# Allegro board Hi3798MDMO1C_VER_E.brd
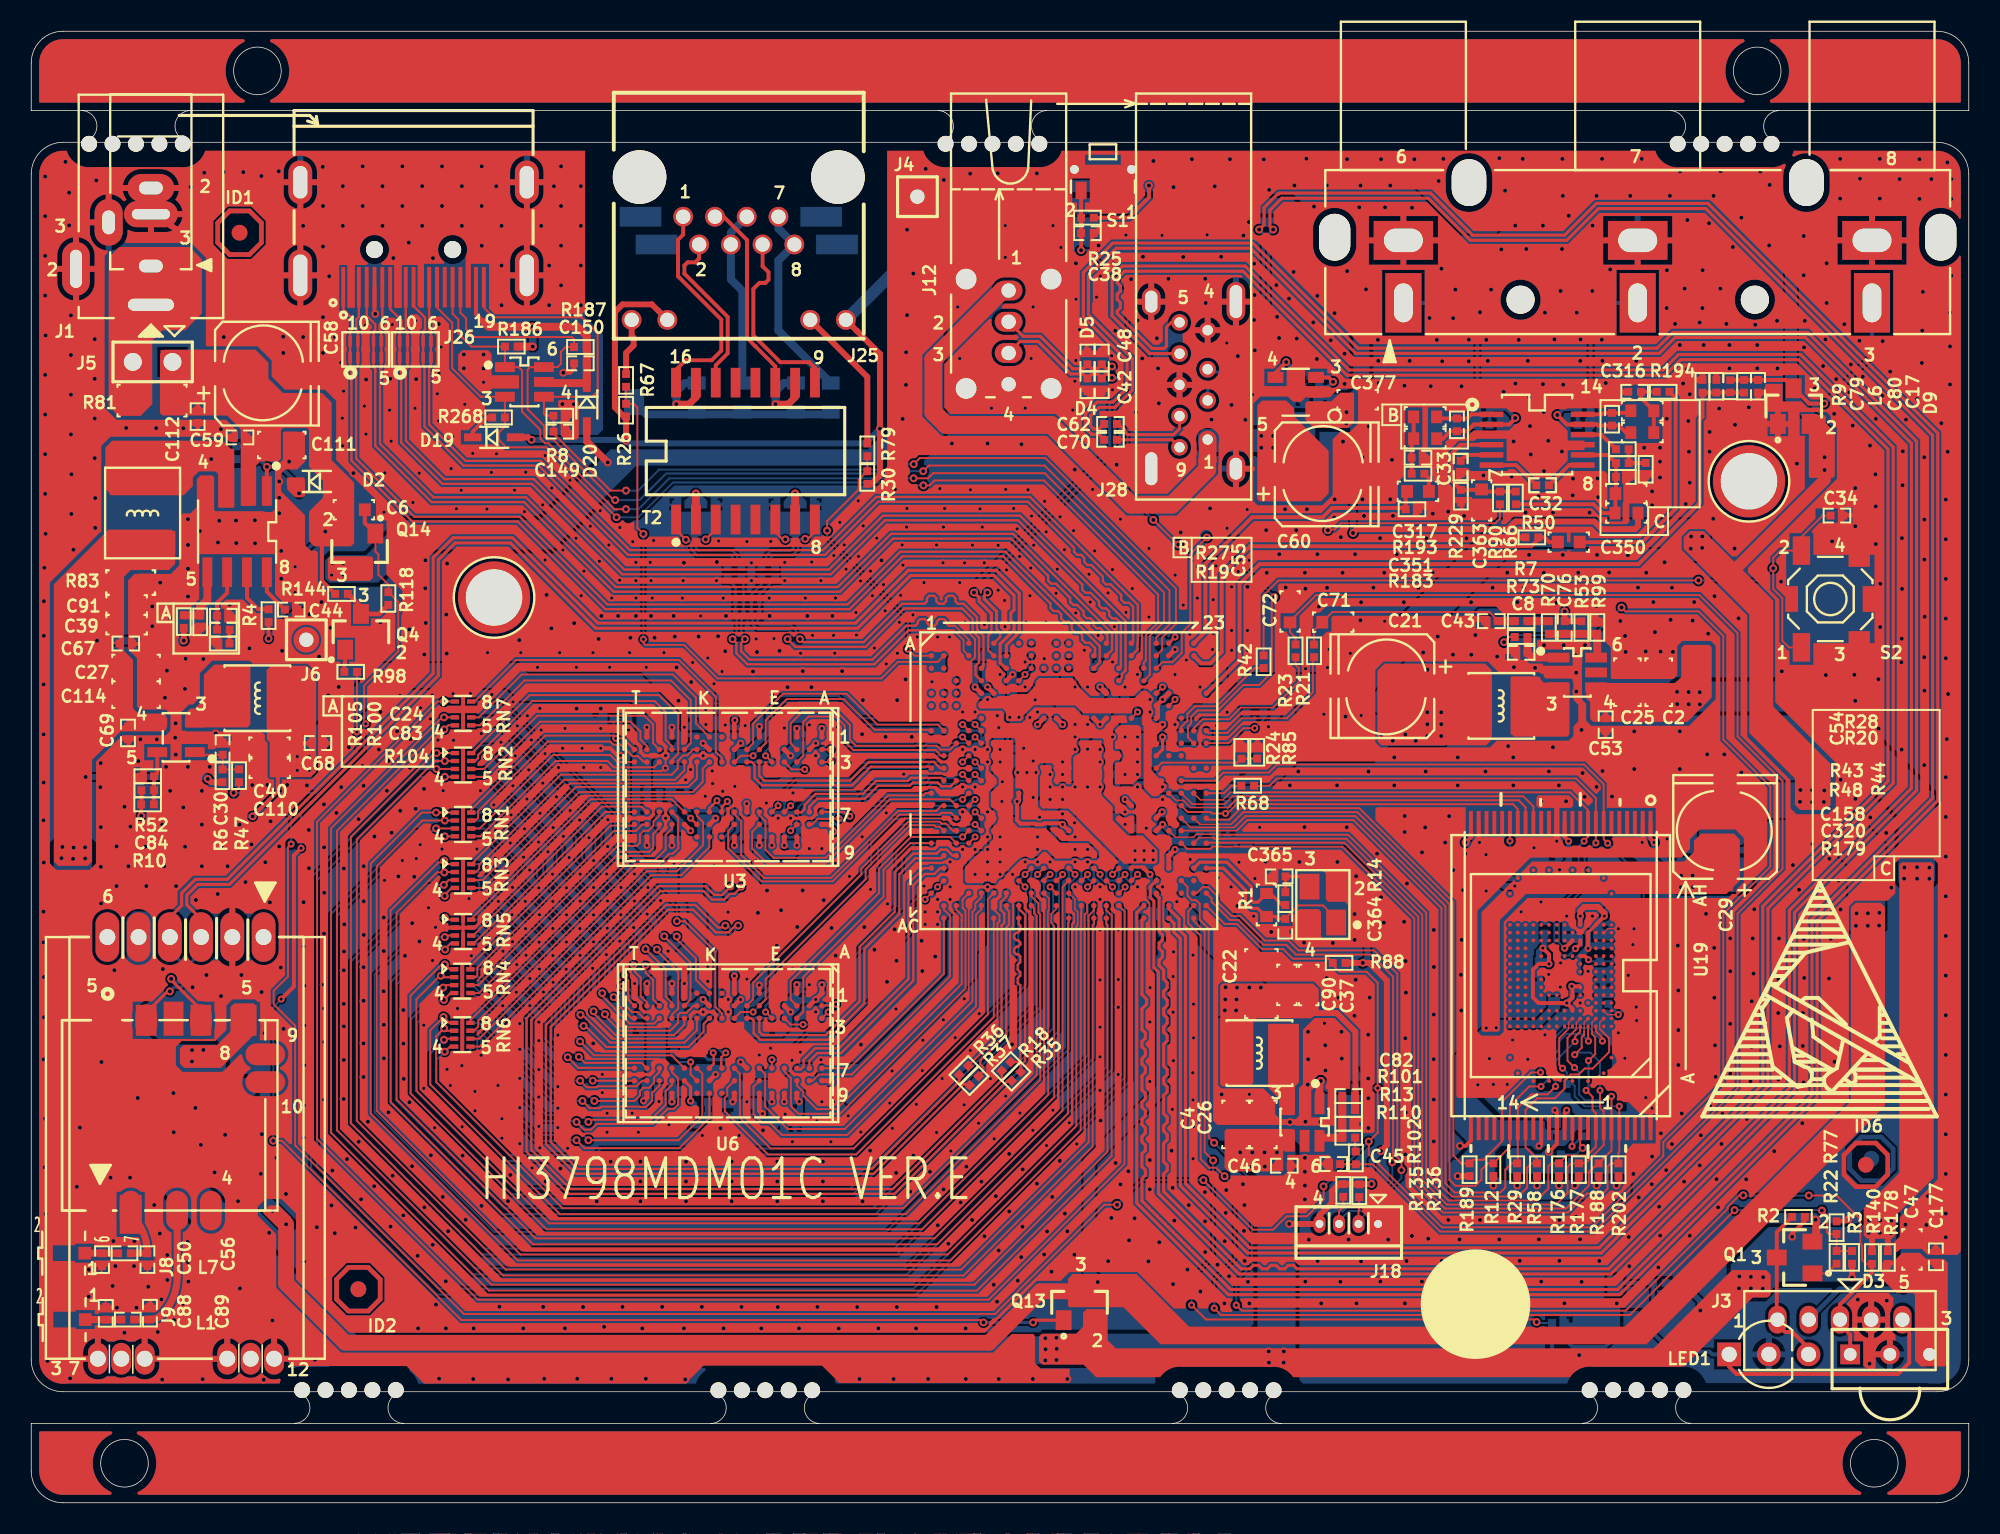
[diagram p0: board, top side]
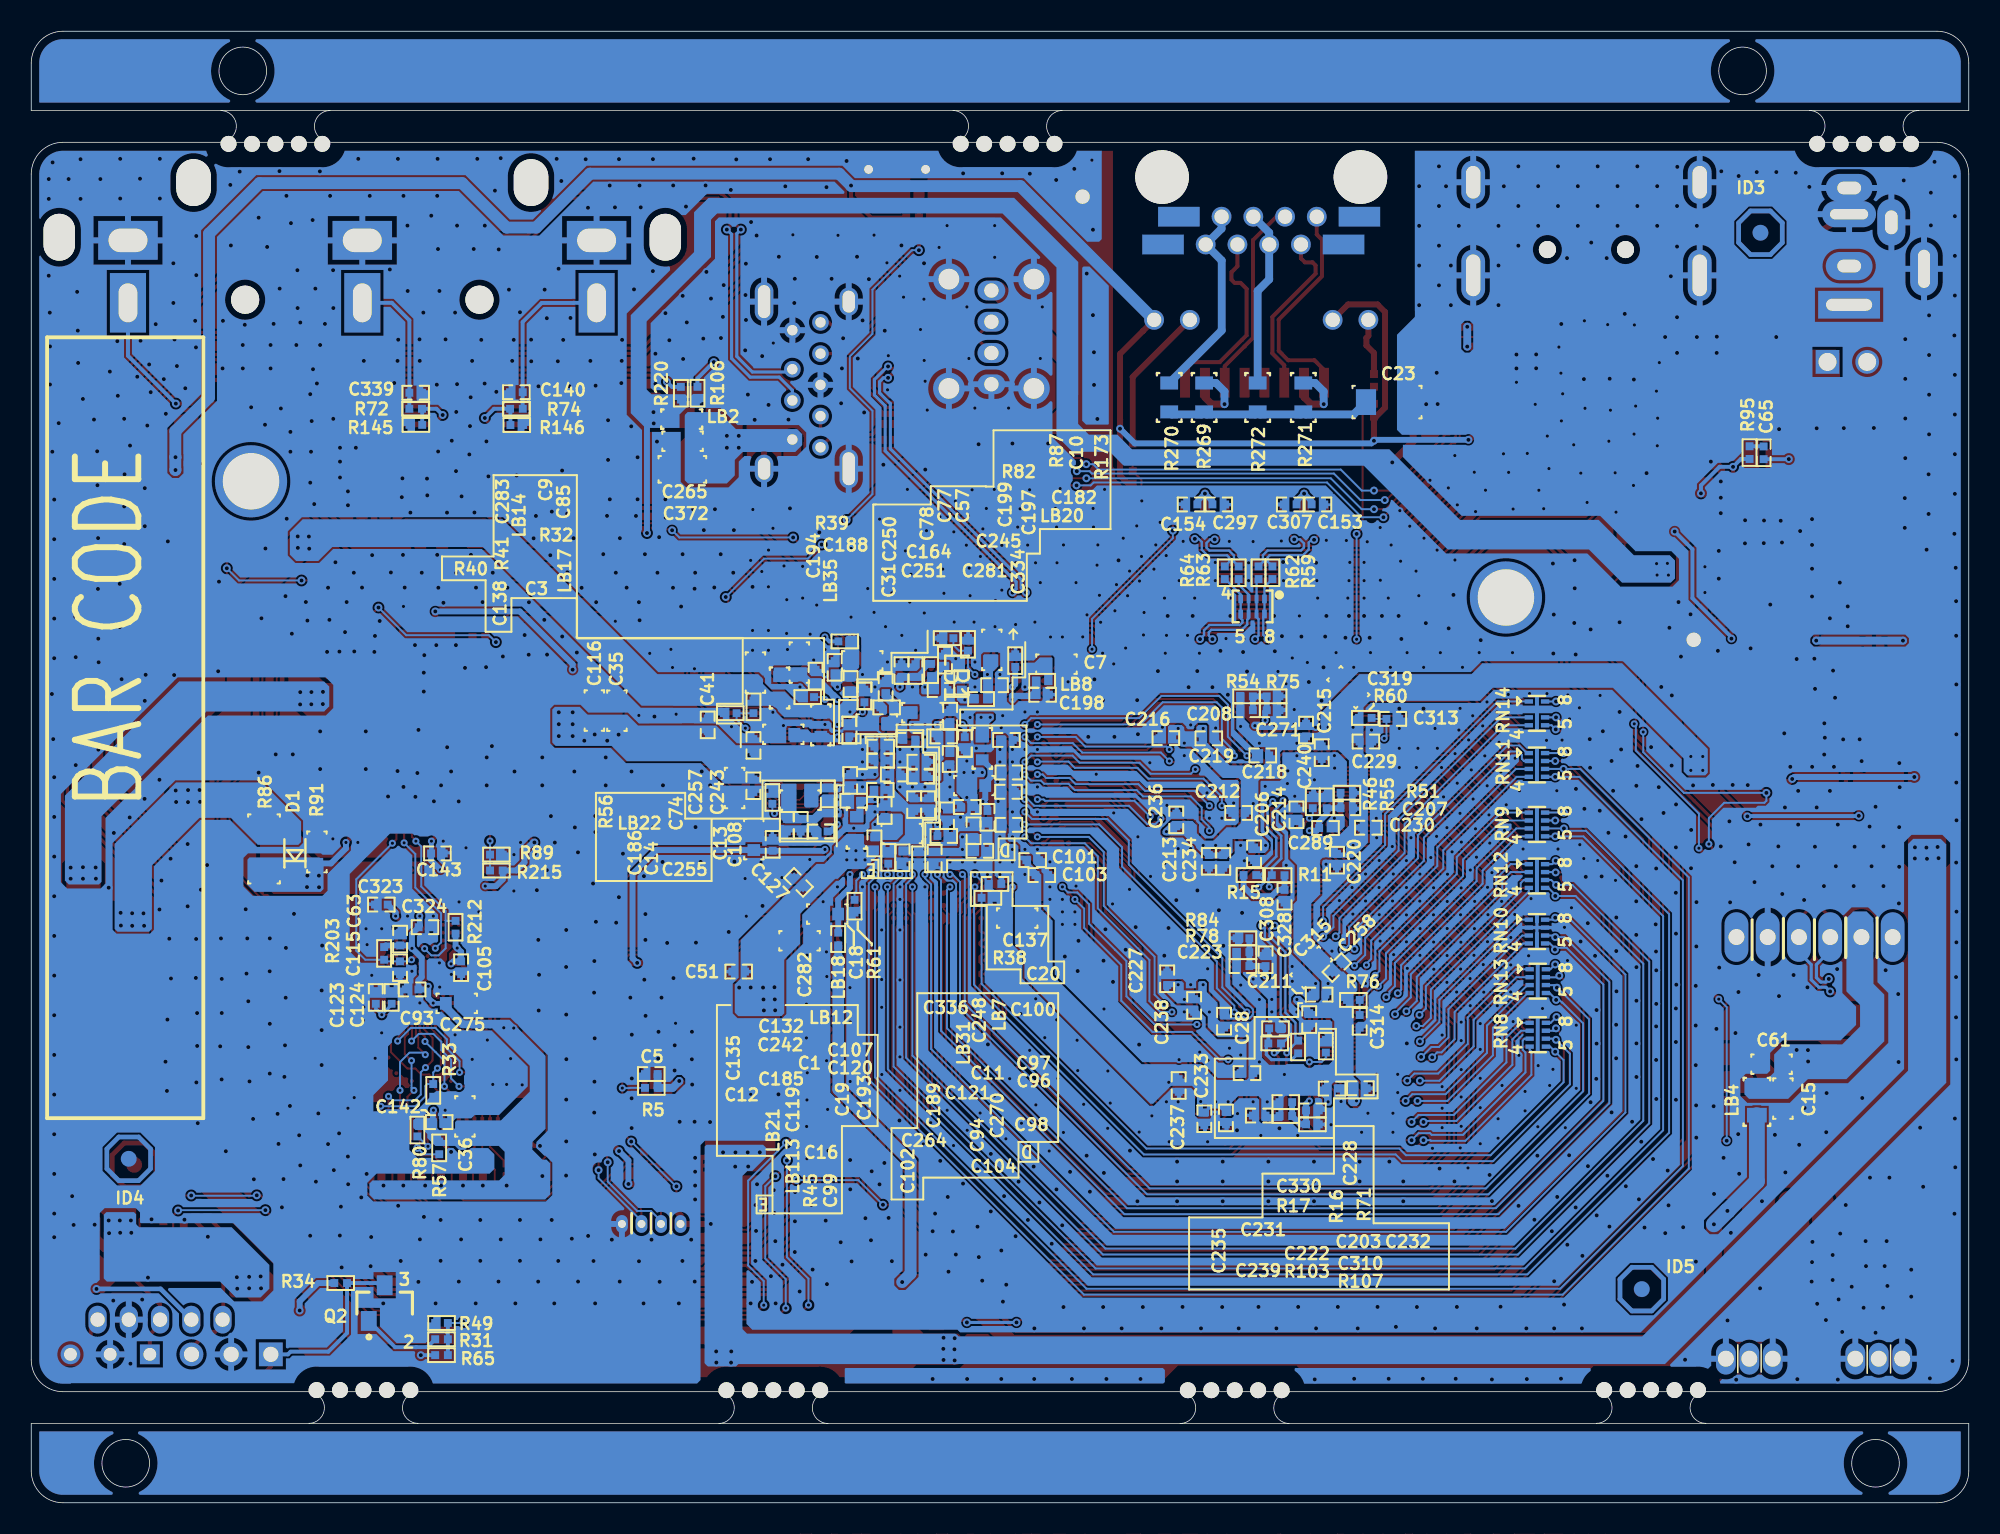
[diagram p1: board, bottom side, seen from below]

Outline 124.03 x 94.22 mm; copper layers: TOP, BOTTOM. Coordinates in mm from the lower left corner of the outline.
Outline path: circle c5.97,2.53 r1.52 ; circle c14.48,91.68 r1.52 ; circle c110.49,91.68 r1.52 ; circle c117.98,2.53 r1.52 ; 0,92.19 arc(0.6,93.63) 2.03,94.22 122,94.22 arc(123.44,93.63) 124.03,92.19 124.03,89.14 0,89.14 0,92.19 ; 0,85.08 arc(0.6,86.52) 2.03,87.11 122,87.11 arc(123.44,86.52) 124.03,85.08 124.03,9.14 arc(123.44,7.71) 122,7.11 2.03,7.11 arc(0.6,7.71) 0,9.14 0,85.08 ; 0,5.08 124.03,5.08 124.03,2.03 arc(123.44,0.6) 122,0 2.03,0 arc(0.6,0.6) 0,2.03 0,5.08

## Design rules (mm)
constraint set DEFAULT: min track width 0.127
net group $4N904: nets $4N904 $4N905
net group $6N188: nets $6N188 XOUT
net group $7N1940: nets $7N1940 USB_BOOT
net group $8N1694: nets $8N1694 DDR_CLK0P
net group $8N1695: nets $8N1695 DDR_CLK0N
net group $8N1696: nets $8N1696 DDR_CLK1P
net group $8N1697: nets $8N1697 DDR_CLK1N
net group $14N447: nets 5V0_MOS $14N447
net group $14N684: nets $14N684 USB3_TXP
net group $14N685: nets $14N685 USB3_TXN
net group $15N955: nets $15N955 LED_RED
net group $15N957: nets $15N957 LED_GREEN
net group $16N1002: nets $16N1002 $16N1006
net group $16N1003: nets $16N1003 $16N1021
net group $16N1028: nets $16N1028 $16N1029
net group $16N1040: nets $16N1040 $16N1041
net group $17N165: nets $17N165 LED0_BASE
net group $17N170: nets $17N170 LED0_LINK_ACT
net group $17N255: nets $17N255 TX+_PHY0
net group $17N256: nets $17N256 TX-_PHY0
net group $17N257: nets $17N257 RX+_PHY0
net group $17N258: nets $17N258 RX-_PHY0
net group $19N506: nets $19N506 HDMI_TX_CEC
net group AVDD33_ADAC: nets AVDD33_ADAC SPDIF_OUT_BOOT_SEL1
net group CLK: nets NF_RDY0_EMMC_RST NF_REN_EMMC_CLK
net group CVBS: nets CVBS CVBS_OUT
net group DIFFPAIR21: nets $17N178 $17N179
net group DIFFPAIR22: nets $17N175 $17N176
net group DIFFPAIR23: nets USB3_RXN USB3_RXP
net group 00: nets GND
net group 01: nets ADAC_VOUTL ADAC_VOUTR AUDIO_L AUDIO_R
net group 5V0_MOS_HDMI: nets 5V0_MOS_HDMI HDMI_TX_SCL HDMI_TX_SDA
net group $4N593: nets $4N593 $4N687 $4N724 $5N549 STANDBY_PWROFF
net group $4N676: nets 1V1_CPU $4N676 $4N677 $4N894 CPU_CTRL
net group $4N714: nets $4N714 $4N715 $4N716 CORE_CTRL
net group $4N903: nets $4N903 $4N923 $4N925
net group $4N906: nets 5V0 $4N906 $4N944 $5N541 $5N542
net group $16N1000: nets $16N873 $16N998 $16N1000 MUTE_CTRL VDD_AUDIO
net group DDR: nets DDR_ADDR0 DDR_ADDR1 DDR_ADDR2 DDR_ADDR3 DDR_ADDR4 DDR_ADDR5 DDR_ADDR6 DDR_ADDR7 DDR_ADDR8 DDR_ADDR9 DDR_ADDR10 DDR_ADDR11 DDR_ADDR12 DDR_ADDR13 DDR_ADDR14 DDR_ADDR15 DDR_BA0 DDR_BA1 DDR_BA2 DDR_CASN DDR_CKE DDR_CSN DDR_DM0 DDR_DM1 DDR_DM2 DDR_DM3 DDR_DQ0 DDR_DQ1 DDR_DQ2 DDR_DQ3 DDR_DQ4 DDR_DQ5 DDR_DQ6 DDR_DQ7 DDR_DQ8 DDR_DQ9 DDR_DQ10 DDR_DQ11 DDR_DQ12 DDR_DQ13 DDR_DQ14 DDR_DQ15 DDR_DQ16 DDR_DQ17 DDR_DQ18 DDR_DQ19 DDR_DQ20 DDR_DQ21 DDR_DQ22 DDR_DQ23 DDR_DQ24 DDR_DQ25 DDR_DQ26 DDR_DQ27 DDR_DQ28 DDR_DQ29 DDR_DQ30 DDR_DQ31 DDR_ODT DDR_RASN DDR_RESETN DDR_WEN
net group DQS: nets DDR_DQS0N DDR_DQS0P DDR_DQS1N DDR_DQS1P DDR_DQS2N DDR_DQS2P DDR_DQS3N DDR_DQS3P
net group HDMI: nets HDMI_TXCN
net group POWER: nets 1V1_CORE 1V5_DDR3 3V3_MOS
net group USB: nets USB0_DM USB0_DP USB1_DM USB1_DP
net group VIN: nets 3V3

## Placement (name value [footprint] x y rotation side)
C1  -  [SC0402]  68.79 46.63 0 bottom
C2  -  [SC0805]  104.18 52.54 90 top
C3  -  [SC0603]  75.89 49.2 0 bottom
C4  -  [SC0805]  77.1 24.22 90 top
C5  -  [SC0402]  84.34 27.45 0 bottom
C6  -  [SC0603]  20.66 63.58 0 top
C7  -  [SC0603]  58.4 53.7 180 bottom
C8  -  [SC0402]  95.38 54.42 180 top
C9  -  [SC0603]  74.86 53.8 90 bottom
C10  -  [SC0603]  62.54 54.61 90 bottom
C11  -  [SC0603]  63.66 45.92 0 bottom
C12  -  [SC0402]  71.38 44.95 0 bottom
C13  -  [SC0603]  77.78 42.49 90 bottom
C14  -  [SC0402]  74.77 43.38 270 bottom
C15  -  [SC0603]  11.9 25.88 270 bottom
C16  -  [SC0603]  68.31 42.85 180 bottom
C17  -  [SC0402]  110.54 71.49 270 top
C18  -  [SC0603]  73.08 37.7 0 bottom
C19  -  [SC0402]  67.51 44.7 270 bottom
C20  -  [SC0603]  60.92 37.44 0 bottom
C21  -  [SAC6666]  86.49 52.29 180 top
C22  -  [SC1206]  78.75 33.24 90 top
C23  -  [SC1206]  37.24 70.48 180 bottom
C24  -  [SC0402]  12.3 56.79 0 top
C25  -  [SC0805]  102.18 52.54 90 top
C26  -  [SC0805]  78.87 24.22 90 top
C27  -  [SC0805]  6.71 53.45 0 top
C28  -  [SC0402]  47.67 30.84 90 bottom
C29  -  [SAC6666]  108.43 43.27 90 top
C30  -  [SC0402]  12.25 48.3 90 top
C31  -  [HSC0402]  71.66 49.48 90 bottom
C32  -  [HSC0402]  96.75 65.15 0 top
C33  -  [HSC0402]  91.51 66.31 90 top
C34  -  [SC0402]  115.6 63.21 0 top
C35  -  [SC0603]  86.54 50.72 90 bottom
C36  -  [SC0603]  96.27 24.74 90 bottom
C37  -  [SC0603]  81.78 33.15 90 top
C38  -  [SC0402]  67.61 81.3 180 top
C39  -  [SC0603]  6.11 56.22 0 top
C40  -  [SC0603]  15.25 48.38 180 top
C41  -  [SC0402]  80.73 49.81 90 bottom
C42  -  [SC0402]  68.53 71.59 270 top
C43  -  [SC0402]  93.47 56.45 180 top
C44  -  [SC0402]  16.64 57.19 0 top
C45  -  [SC0402]  83.38 21.69 180 top
C46  -  [SC0402]  80.21 21.58 0 top
C47  -  [SC0603]  120.4 16.22 90 top
C48  -  [SC0402]  68.53 73.3 90 top
C50  -  [SC0402]  4.53 15.57 270 top
C51  -  [SC0402]  78.75 34.01 0 bottom
C53  -  [SC0402]  100.79 49.82 270 top
C54  -  [SC0402]  101.2 69.38 90 top
C55  -  [SC0402]  91.26 69.02 270 top
C56  -  [SC0402]  7.44 15.57 270 top
C57  -  [SC0402]  67.43 53.29 90 bottom
C58  -  [SAC6666]  15.09 72.3 0 top
C59  -  [SC0402]  13.36 68.22 180 top
C60  -  [SAC6666]  82.93 65.85 0 top
C61  -  [SC0603]  12.62 28.08 0 bottom
C62  -  [SC0402]  69.09 69.08 180 top
C63  -  [SC0402]  100.42 36.09 90 bottom
C65  -  [SC0402]  13.13 67.23 270 bottom
C67  -  [SC0402]  6.06 55.02 0 top
C68  -  [SC0402]  18.35 48.65 0 top
C69  -  [SC0402]  6.19 49.29 270 top
C70  -  [SC0402]  69.09 68.06 180 top
C71  -  [SC0603]  83.35 56.39 0 top
C72  -  [SC0603]  80.58 57.07 90 top
C74  -  [SC0402]  73.04 45.39 270 bottom
C76  -  [SC0402]  98.17 56.04 90 top
C77  -  [SC0402]  68.32 53.29 90 bottom
C78  -  [SC0402]  69.34 52.22 90 bottom
C79  -  [SC0402]  107.87 71.49 90 top
C80  -  [SC0402]  109.65 71.49 90 top
C82  -  [SC0402]  84.33 26.04 0 top
C83  -  [SC0402]  12.3 55.91 0 top
C84  -  [SC0402]  7.46 45.63 180 top
C85  -  [SC0402]  73.82 52.93 90 bottom
C88  -  [SC0402]  4.77 12.13 90 top
C89  -  [SC0402]  7.6 12.14 90 top
C90  -  [SC0603]  80.38 33.16 90 top
C91  -  [SC0603]  6.11 57.49 0 top
C93  -  [SC0402]  99.65 32.87 0 bottom
C94  -  [SC0402]  63.71 43.03 90 bottom
C96  -  [SC0402]  61.47 45.52 180 bottom
C97  -  [SC0402]  61.45 46.76 180 bottom
C98  -  [SC0402]  61.45 43.41 180 bottom
C99  -  [SC0402]  68.26 41.3 270 bottom
C100  -  [SC0402]  61.6 48.84 180 bottom
C101  -  [SC0402]  59.93 41.15 180 bottom
C102  -  [SC0402]  66.2 41.27 270 bottom
C103  -  [SC0402]  59.34 40.19 180 bottom
C104  -  [SC0402]  63.31 41.74 180 bottom
C105  -  [SC0402]  96.51 34.26 270 bottom
C107  -  [SC0402]  67.09 47.45 180 bottom
C108  -  [SC0402]  76.57 42.16 90 bottom
C110  -  [SC0603]  15.27 47.02 180 top
C111  -  [SC0805]  16.04 67.73 0 top
C112  -  [SC0402]  10.65 69.55 270 top
C114  -  [SC0805]  6.71 51.74 0 top
C115  -  [SC0402]  100.43 34.26 270 bottom
C116  -  [SC0603]  87.98 50.73 90 bottom
C119  -  [SC0402]  69.4 44.32 90 bottom
C120  -  [HSC0402]  67.09 46.51 180 bottom
C121  -  [SC0402]  64.12 44.55 180 bottom
C123  -  [SC0402]  101.97 32.36 90 bottom
C124  -  [SC0402]  100.96 32.36 90 bottom
C127  -  [SC0402]  74.91 39.73 45 bottom
C132  -  [SC0402]  69.65 48.41 180 bottom
C135  -  [SC0402]  71.61 46.25 270 bottom
C137  -  [SC0402]  62.34 39.62 0 bottom
C138  -  [SC0402]  77.8 48.49 90 bottom
C140  -  [SC0402]  92.98 71.11 0 bottom
C142  -  [SC0402]  97.92 24.37 180 bottom
C143  -  [SC0402]  98.03 41.58 180 bottom
C149  -  [SC0402]  33.84 68.59 0 top
C150  -  [SC0402]  35.16 72.96 180 top
C153  -  [SC0402]  41.66 63.92 180 bottom
C154  -  [SC0402]  49.79 63.92 0 bottom
C158  -  [SC0402]  101.86 65.68 0 top
C164  -  [SC0402]  69.27 50.93 0 bottom
C177  -  [SC0402]  121.93 15.75 90 top
C182  -  [SC0402]  62.36 52.35 180 bottom
C185  -  [SC0402]  69.68 45.64 180 bottom
C186  -  [SC0402]  75.66 43.38 270 bottom
C188  -  [SC0603]  70.83 53.91 180 bottom
C189  -  [SC0402]  65.41 43.99 270 bottom
C193  -  [SC0402]  66.62 44.7 270 bottom
C194  -  [SC0402]  72.6 53.49 90 bottom
C197  -  [SC0402]  64.5 52.45 90 bottom
C198  -  [SC0402]  59.29 51.74 180 bottom
C199  -  [SC0402]  65.54 53.95 90 bottom
C203  -  [SC0402]  40.75 26.52 180 bottom
C206  -  [SC0402]  45.75 41.55 270 bottom
C207  -  [SC0402]  39.81 44.47 0 bottom
C208  -  [SC0402]  46.23 50.75 180 bottom
C211  -  [SC0402]  41.59 32.54 0 bottom
C212  -  [SC0402]  46.74 44.17 0 bottom
C213  -  [SC0402]  48.65 41.07 270 bottom
C214  -  [SC0402]  43.04 44.05 90 bottom
C215  -  [SC0402]  41.42 48.03 270 bottom
C216  -  [SC0402]  51.4 48.96 0 bottom
C218  -  [SC0402]  45.19 47.85 0 bottom
C219  -  [SC0402]  48.65 48.95 180 bottom
C220  -  [SC0402]  40.44 41.15 270 bottom
C222  -  [SC0402]  43.72 25.65 180 bottom
C223  -  [SC0402]  46.46 34.37 180 bottom
C227  -  [SC0402]  51.31 33.55 90 bottom
C228  -  [SC0402]  42.22 30.94 270 bottom
C229  -  [SC0402]  38.59 48.74 180 bottom
C230  -  [SC0402]  38.44 43.22 180 bottom
C231  -  [SC0402]  46.21 27.51 0 bottom
C232  -  [SC0402]  38.94 26.54 180 bottom
C233  -  [SC0402]  48.94 24.59 270 bottom
C234  -  [SC0402]  47.72 41.06 270 bottom
C235  -  [SC0402]  47.55 24.64 270 bottom
C236  -  [SC0402]  50.73 43.72 90 bottom
C237  -  [SC0402]  50.58 26.72 270 bottom
C238  -  [SC0402]  49.59 31.84 270 bottom
C239  -  [SC0402]  45.42 24.79 0 bottom
C240  -  [SC0402]  42.42 49.48 90 bottom
C242  -  [HSC0402]  69.65 47.52 180 bottom
C243  -  [SC0402]  77.8 45.91 270 bottom
C245  -  [SC0402]  65.79 52.04 180 bottom
C248  -  [HSC0402]  64.27 48.62 270 bottom
C250  -  [HSC0402]  70.69 51.66 270 bottom
C251  -  [SC0603]  69.91 49.86 0 bottom
C255  -  [HSC0402]  73.46 42.98 180 bottom
C257  -  [SC0603]  79.01 45.77 270 bottom
C258  -  [SC0402]  40.45 34.27 135 bottom
C264  -  [SC0402]  65.61 42.7 180 bottom
C265  -  [SC0603]  82.34 67.97 0 bottom
C270  -  [SC0402]  62.82 43.89 270 bottom
C271  -  [SC0402]  44.53 50.75 180 bottom
C275  -  [SC0603]  96.79 31.98 180 bottom
C281  -  [SC0603]  66.99 50.6 180 bottom
C282  -  [SC0603]  74.85 35.98 180 bottom
C283  -  [SC0603]  77.67 53.16 90 bottom
C289  -  [SC0402]  41.18 43.21 180 bottom
C297  -  [SC0402]  48.01 63.92 180 bottom
C307  -  [SC0402]  43.44 63.92 0 bottom
C308  -  [SC0402]  45.02 34.77 90 bottom
C310  -  [SC0402]  42.02 25.12 180 bottom
C313  -  [SC0402]  36.87 50.19 180 bottom
C314  -  [SC0402]  38.99 30.83 270 bottom
C315  -  [SC0603]  42.08 34.28 315 bottom
C316  -  [SC0402]  102.64 71.14 180 top
C317  -  [SC0402]  88.77 66.92 0 top
C319  -  [SC0603]  39.72 52.21 45 bottom
C320  -  [SC0603]  102.11 64.62 0 top
C323  -  [SC0402]  101.62 38.3 0 bottom
C324  -  [SC0402]  98.83 36.85 180 bottom
C328  -  [SC0402]  43.8 38.84 270 bottom
C330  -  [SC0402]  44.38 30.38 180 bottom
C334  -  [SC0402]  65.21 50.37 90 bottom
C336  -  [SC0402]  65.61 49.07 0 bottom
C339  -  [SC0402]  99.42 71.08 180 bottom
C350  -  [SC0603]  98.42 61.51 180 top
C351  -  [SC0603]  88.77 64.76 0 top
C363  -  [SC0603]  92.85 64.18 270 top
C364  -  [SC0402]  80.28 36.98 270 top
C365  -  [SC0402]  79.89 40.11 180 top
C372  -  [SC0805]  82.35 66.17 0 bottom
C377  -  [SC0603]  84.91 70.62 0 top
D1  -  [HSOD323A]  107.15 41.59 270 bottom
D2  -  [HSOD323A]  18.29 65.39 180 top
D3  -  [SEN3-100C]  118.98 9.5 0 top
D4  -  [SC0402]  67.61 71.59 270 top
D5  -  [SC0402]  67.61 73.3 90 top
D9  -  [SOT23]  112.83 70.22 0 top
D19  -  [HSOD323A]  29.64 68.22 180 top
D20  -  [HSOD323A]  35.57 70.32 90 top
ID1  -  [ID-BOARD]  13.34 81.32 0 top
ID2  -  [ID-BOARD]  20.94 13.67 0 top
ID3  -  [ID-BOARD]  13.34 81.32 180 bottom
ID4  -  [ID-BOARD]  117.79 22.02 180 bottom
ID5  -  [ID-BOARD]  20.93 13.68 180 bottom
ID6  -  [ID-BOARD]  117.44 21.64 0 top
J1  -  [PWC3-RF-A]  7.66 76.71 90 top
J2  VALUE  [SIP12-2_0MM-1827]  9.87 22.72 270 top
J3  -  [SIP5-2MM]  111.79 11.72 0 top
J4  -  [SIP-1P]  56.73 83.63 0 top
J5  -  [SIP-2P]  7.77 73.05 180 top
J6  -  [SIP-1P]  17.61 55.26 0 top
J8  -  [HSCOX-AMC-TM-A]  2.08 15.98 270 top
J9  -  [HSCOX-AMC-TM-A]  2.11 11.73 270 top
J10  -  [DC-002]  7.66 79.19 0 top
J12  -  [USB4-200-1907]  62.57 77.62 270 top
J18  -  [WBC0104-49T]  86.22 17.85 180 top
J25  -  [MJ8-RLY]  41.74 82.35 0 top
J26  -  [WBC0119-20R-A]  24.47 82.99 180 top
J28  -  [RUSB9-180-0726A]  75.31 68.08 180 top
J34  -  [AV3-8-5-1]  102.84 80.08 270 top
L1  -  [SL0402]  6.18 11.73 0 top
L2  -  [SWPA4020S]  94.11 51.03 180 top
L3  -  [SWPA4020S]  78.63 28.79 180 top
L4  -  [SWPA4020S]  14.48 51.52 0 top
L5  -  [SWPA5040S]  7.12 63.37 270 top
L6  -  [SL0402]  108.76 71.49 90 top
L7  -  [SL0402]  5.97 15.97 0 top
LB1  -  [SL0402]  66.43 53.31 270 bottom
LB2  -  [SL0603]  82.39 69.39 0 bottom
LB4  -  [SL0805]  13.56 25.67 270 bottom
LB7  -  [SL0603]  63.15 48.31 90 bottom
LB8  -  [SL0402]  59.32 52.63 0 bottom
LB12  -  [SL0402]  67.81 48.85 180 bottom
LB14  -  [SL0603]  76.13 52.17 90 bottom
LB17  -  [SL0603]  73.49 49.81 90 bottom
LB18  -  [SL0402]  72.38 36.1 90 bottom
LB20  -  [SL0402]  63.23 51.46 180 bottom
LB21  -  [SL0603]  71.2 43.2 90 bottom
LB22  -  [SL0603]  74.81 44.99 0 bottom
LB31  -  [SL0402]  65.23 47.62 90 bottom
LB35  -  [SL0402]  71.58 52.43 90 bottom
LB113  -  [SL0402]  70.06 42.22 90 bottom
LED1  -  [LED3C-100C]  108.69 9.5 0 top
M20  VALUE  [HOLE182-142]  29.63 57.97 0 top
M21  VALUE  [HOLE182-142]  109.96 65.4 0 top
NOREF  -  []  413.93 99.16 0 top
NOREF#2  -  [unnamed#2]  6.7 88.15 180 top
NOREF#3  -  []  279.21 -69.88 0 top
NOREF#4  -  [unnamed#2]  46.99 6.08 0 top
NOREF#5  -  [unnamed#2]  61.53 88.15 180 top
NOREF#6  -  []  431.85 220.39 0 top
NOREF#7  -  []  2.19 7.11 90 top
NOREF#8  -  [unnamed#2]  108.4 88.14 180 top
NOREF#9  -  []  -120.02 -141.51 0 top
NOREF#10  -  []  420.83 155.16 0 top
NOREF#11  -  []  4.27 0 90 top
NOREF#12  -  [unnamed#2]  102.77 6.09 0 top
NOREF#13  -  []  -0.01 9.38 0 top
NOREF#14  -  [unnamed#2]  76.53 6.08 0 top
NOREF#15  -  []  92.96 12.94 0 top
NOREF#16  -  [unnamed#2]  20.34 6.09 0 top
NOREF#17  -  []  73.36 -6.11 180 bottom
Q1  -  [SOT23]  112.88 15.7 90 top
Q2  -  [SOT23]  101.41 12.79 180 bottom
Q4  -  [SOT23]  21.11 55.77 0 top
Q13  -  [SOT23]  67.11 12.83 0 top
Q14  -  [SOT23]  21.02 60.91 180 top
R1  -  [SR0603]  79.08 38.28 270 top
R2  -  [SR0402]  113.13 18.3 180 top
R3  -  [SR0402]  116.56 15.71 90 top
R4  -  [SR0402]  15.19 56.81 90 top
R5  -  [SR0402]  84.34 26.57 180 bottom
R6  -  [SR0402]  12.25 46.55 90 top
R7  -  [SR0402]  95.38 56.45 180 top
R8  -  [SR0402]  33.84 69.6 180 top
R9  -  [SR0402]  106.98 71.49 90 top
R10  -  [SR0402]  7.45 44.72 180 top
R11  -  [SR0402]  44.21 40.18 180 bottom
R12  -  [SR0402]  93.6 21.33 90 top
R13  -  [SR0402]  84.33 24.26 180 top
R14  -  [SR0402]  80.28 38.68 90 top
R15  -  [SR0402]  46.02 40.19 180 bottom
R16  -  [SR0402]  42.93 29.18 270 bottom
R17  -  [SR0402]  44.43 29.41 180 bottom
R18  -  [SR0402]  62.41 27.94 45 top
R19  -  [SR0603]  89.23 68.14 0 top
R20  -  [SR0603]  103.13 68.53 0 top
R21  -  [SR0402]  82.12 54.55 270 top
R22  -  [SR0402]  115.57 15.71 270 top
R23  -  [SR0402]  80.94 54.55 270 top
R24  -  [SR0402]  77.47 48.05 90 top
R25  -  [SR0402]  67.61 82.29 180 top
R26  -  [SR0402]  38.08 69.96 90 top
R27  -  [SR0603]  89.23 69.53 0 top
R28  -  [SR0603]  103.13 69.92 0 top
R29  -  [SR0402]  95.12 21.33 90 top
R30  -  [SR0402]  53.52 65.65 90 top
R31  -  [SR0402]  97.77 10.47 0 bottom
R32  -  [SR0402]  74.33 51.59 180 bottom
R33  -  [SR0402]  98.3 26.41 270 bottom
R34  -  [SR0402]  104.22 14.07 180 bottom
R35  -  [SR0402]  63.05 27.3 45 top
R36  -  [SR0402]  59.7 27.69 45 top
R37  -  [SR0402]  60.36 27.03 45 top
R38  -  [SR0402]  62.79 38.73 0 bottom
R39  -  [SR0402]  71.95 55.16 180 bottom
R40  -  [SR0402]  79.28 50.56 0 bottom
R41  -  [SR0402]  77.8 50.96 90 bottom
R42  -  [SR0402]  78.89 53.85 270 top
R43  -  [SR0402]  101.85 67.46 0 top
R44  -  [SR0402]  103.35 66.18 270 top
R45  -  [SR0402]  69.17 41.33 90 bottom
R46  -  [SR0402]  41.99 44.88 270 bottom
R47  -  [SR0402]  13.3 46.56 90 top
R48  -  [SR0402]  101.86 66.57 0 top
R49  -  [SR0402]  97.77 11.51 0 bottom
R50  -  [SR0402]  96.06 61.81 180 top
R51  -  [SR0402]  39.81 45.46 0 bottom
R52  -  [SR0402]  7.46 46.52 180 top
R53  -  [SR0402]  99.23 56.04 90 top
R54  -  [SR0402]  46.23 51.64 180 bottom
R55  -  [SR0402]  41.1 44.88 90 bottom
R56  -  [SR0402]  76.59 45.16 270 bottom
R57  -  [SR0402]  97.92 22.72 90 bottom
R58  -  [SR0402]  96.39 21.33 90 top
R59  -  [SR0402]  44.58 59.55 90 bottom
R60  -  [SR0402]  38.63 50.26 180 bottom
R61  -  [SR0402]  71.33 38.2 90 bottom
R62  -  [SR0402]  45.47 59.55 90 bottom
R63  -  [SR0402]  46.74 59.55 90 bottom
R64  -  [SR0402]  47.62 59.55 90 bottom
R65  -  [SR0402]  97.77 9.45 180 bottom
R66  -  [SR0402]  95.04 64.34 270 top
R67  -  [SR0402]  38.08 71.87 270 top
R68  -  [SR0402]  77.88 45.91 180 top
R70  -  [SR0402]  97.15 56.04 90 top
R71  -  [SR0402]  41.15 29.24 270 bottom
R72  -  [HSR0402]  99.42 70.05 0 bottom
R73  -  [SR0402]  95.38 55.44 0 top
R74  -  [HSR0402]  92.97 70.05 0 bottom
R75  -  [SR0402]  44.53 51.64 180 bottom
R76  -  [SR0402]  39.4 32.2 180 bottom
R77  -  [SR0402]  115.57 17.62 90 top
R78  -  [SR0402]  46.46 35.25 180 bottom
R79  -  [SR0402]  53.52 67.42 270 top
R80  -  [SR0402]  99.31 23.87 270 bottom
R81  2.7  [SR1206]  7.73 70.57 0 top
R82  -  [SR0402]  65.41 55.36 180 bottom
R83  -  [SR0805]  6.36 58.92 0 top
R84  -  [SR0402]  46.46 36.14 0 bottom
R85  -  [SR0402]  78.48 48.05 90 top
R86  2.7  [SR1206]  109.13 41.87 270 bottom
R87  -  [SR0402]  64.07 54.97 270 bottom
R88  -  [SR0402]  83.73 34.57 0 top
R89  -  [SR0402]  94.25 41.5 180 bottom
R90  -  [SR0402]  94.02 64.34 90 top
R91  -  [SR0603]  105.75 41.67 90 bottom
R95  -  [SR0402]  14.03 67.24 90 bottom
R98  -  [SR0402]  20.45 53.2 180 top
R99  -  [SR0402]  100.25 56.05 270 top
R100  -  [SR0402]  10.82 56.41 270 top
R101  -  [SR0402]  84.33 25.15 0 top
R102  -  [SR0402]  84.8 22.08 270 top
R103  -  [SR0402]  43.72 24.76 180 bottom
R104  -  [SR0402]  12.28 55.02 180 top
R105  -  [SR0402]  9.77 56.42 270 top
R106  -  [SR0402]  81.38 71.05 90 bottom
R107  -  [SR0402]  42.02 24.23 180 bottom
R110  -  [SR0402]  84.34 23.38 0 top
R118  -  [SR0402]  22.86 57.9 270 top
R135  -  [SR0402]  83.99 20 270 top
R136  -  [SR0402]  85.01 19.98 90 top
R140  -  [SR0402]  117.84 15.7 90 top
R144  -  [SR0402]  19.86 58.19 0 top
R145  -  [SR0402]  99.41 69.02 0 bottom
R146  -  [SR0402]  92.95 69.01 180 bottom
R173  -  [SR0402]  61.04 53.92 90 bottom
R176  -  [SR0402]  97.8 21.33 90 top
R177  -  [SR0402]  99.07 21.33 90 top
R178  -  [SR0402]  118.85 15.7 90 top
R179  -  [SR0603]  102.12 63.37 180 top
R183  -  [SR0402]  88.39 63.62 0 top
R186  -  [SR0402]  30.73 74.03 0 top
R187  -  [SR0402]  35.15 74.01 0 top
R188  -  [SR0402]  100.34 21.33 90 top
R189  -  [SR0402]  92.08 21.33 90 top
R193  -  [SR0402]  88.78 65.89 180 top
R194  -  [SR0402]  104.47 71.14 0 top
R202  -  [SR0402]  101.61 21.33 90 top
R203  -  [SR0402]  101.44 35.18 270 bottom
R212  -  [SR0402]  96.87 36.85 90 bottom
R215  -  [SR0402]  94.25 40.48 0 bottom
R220  -  [SR0402]  82.45 71.05 270 bottom
R229  -  [SR0402]  91.52 64.45 270 top
R268  -  [SR0402]  29.92 69.49 0 top
R269  -  [SR0805]  48.95 70.78 90 bottom
R270  -  [SR0805]  51.18 70.78 90 bottom
R271  -  [SR0805]  42.6 70.78 90 bottom
R272  -  [SR0805]  45.52 70.78 90 bottom
RN1  -  [SRN8-0804]  27.64 43.43 270 top
RN2  -  [SRN8-0804]  27.64 47.24 270 top
RN3  -  [SRN8-0804]  27.64 40.13 270 top
RN4  -  [SRN8-0804]  27.59 33.4 270 top
RN5  -  [SRN8-0804]  27.64 36.57 270 top
RN6  -  [SRN8-0804]  27.59 29.97 270 top
RN7  -  [SRN8-0804]  27.64 50.54 270 top
RN8  -  [SRN8-0804]  27.59 29.97 270 bottom
RN9  -  [SRN8-0804]  27.64 43.43 270 bottom
RN10  -  [SRN8-0804]  27.64 36.57 270 bottom
RN11  -  [SRN8-0804]  27.64 47.24 270 bottom
RN12  -  [SRN8-0804]  27.64 40.13 270 bottom
RN13  -  [SRN8-0804]  27.59 33.4 270 bottom
RN14  -  [SRN8-0804]  27.64 50.54 270 bottom
S1  -  [RSTSW5-R]  68.61 84.95 180 top
S2  -  [SPSW6-T]  115.17 57.87 90 top
T2  -  [STFM16-50-285]  45.72 67.34 0 top
U1  VALUE  [TFBGA395-32-2323]  66.42 46.23 270 top
U2  -  [CDTWIFI]  8.86 24.81 90 top
U3  -  [BGA96-32-1609I]  44.61 45.83 180 top
U4  -  [SOT23A-6L]  31.57 71.77 270 top
U5  -  [SGM8903]  96.4 68.39 270 top
U6  -  [BGA96-32-1609I]  44.61 29.42 180 top
U7  VALUE  [CDTWIFI10]  8.48 24.81 90 top
U8  -  [RN8-0402]  45.85 57.39 0 bottom
U11  SY7208  [SOT23_6]  98.97 53.17 270 top
U13  SY7208  [SOT23_6]  81.52 24.38 180 top
U14  MP1484  [SOIC8N]  13.18 62.19 180 top
U15  -  [SOT23_5]  9.27 49.01 90 top
U19  -  [SOP48-20-720B]  97.91 33.75 180 top
U22  -  [BGA169-BGA153-0_5MM]  97.91 33.75 90 top
U23  -  [DFN2510P10E]  21.41 73.85 0 top
U24  -  [DFN2510P10E]  24.59 73.85 0 top
U26  -  [SOT23-5]  80.95 71.11 90 top
X2  -  [X288]  82.68 38.3 90 top

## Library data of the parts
C1 C5 C8 C12 C14 C17 C19 C24 C28 C30 C34 C38 C41-C46 C48 C50 C51 C53-C57 C59 C62 C63 C65 C67-C70 C74 C76-C80 C82-C85 C88 C89 C93 C94 C96-C105 C107 C108 C112 C115 C119 C121 C123 C124 C127 C132 C135 C137 C138 C140 C142 C143 C149 C150 C153 C154 C158 C177 C182 C185 C186 C189 C193 C194 C197-C199 C203 C206-C208 C211-C216 C218-C220 C222 C223 C227-C240 C243 C245 C258 C264 C270 C271 C289 C297 C307 C308 C310 C313 C314 C316 C317 C323 C324 C328 C330 C334 C336 C339 C364 C365 D4 D5 = SC0402
C2 C4 C25-C27 C111 C114 C372 = SC0805
C3 C6 C7 C9-C11 C13 C15 C16 C18 C20 C35-C37 C39 C40 C47 C61 C71 C72 C90 C91 C110 C116 C188 C251 C257 C265 C275 C281-C283 C315 C319 C320 C350 C351 C363 C377 = SC0603
C21 C29 C58 C60 = SAC6666
C22 C23 = SC1206
C31-C33 C120 C242 C248 C250 C255 = HSC0402
C164 = SC0402: signal model: SC0402_10PF/NC
D1 D2 D19 D20 = HSOD323A
D3 = SEN3-100C
D9 Q1 Q2 Q4 Q13 Q14 = SOT23
ID1-ID6 = ID-BOARD
J1 = PWC3-RF-A
J2 = SIP12-2_0MM-1827
J3 = SIP5-2MM
J4 J6 = SIP-1P
J5 = SIP-2P
J8 J9 = HSCOX-AMC-TM-A
J10 = DC-002
J12 = USB4-200-1907
J18 = WBC0104-49T
J25 = MJ8-RLY
J26 = WBC0119-20R-A
J28 = RUSB9-180-0726A
J34 = AV3-8-5-1
L1 L6 L7 LB1 LB8 LB12 LB18 LB20 LB31 LB35 LB113 = SL0402
L2-L4 = SWPA4020S
L5 = SWPA5040S
LB2 LB7 LB14 LB17 LB21 LB22 = SL0603
LB4 = SL0805
LED1 = LED3C-100C
M20 M21 = HOLE182-142
R1 R19 R20 R27 R28 R91 R179 = SR0603
R2-R18 R21-R26 R30-R35 R39-R44 R47-R53 R56 R57 R59-R68 R70 R71 R73 R75-R80 R82 R84 R85 R87-R90 R95 R99-R107 R110 R118 R145 R146 R173 R176 R177 R183 R186-R189 R193 R194 R202 R203 R212 R220 R268 = SR0402
R29 R178 = SR0402: signal model: SR0402_75
R36-R38 R45 R46 = SR0402: signal model: SR0402_33
R54 R55 = SR0402: signal model: SR0402_240
R58 R98 R135 R136 R140 = SR0402: signal model: SR0402_10K
R72 R74 = HSR0402
R81 R86 = SR1206: signal model: DEFAULT_RESISTOR_2.7OHM_1_2
R83 R269-R272 = SR0805
R144 R215 R229 = SR0402: signal model: SR0402_4.7K
RN1-RN14 = SRN8-0804
S1 = RSTSW5-R
S2 = SPSW6-T
T2 = STFM16-50-285
U1 = TFBGA395-32-2323
U2 = CDTWIFI
U3 U6 = BGA96-32-1609I
U4 = SOT23A-6L
U5 = SGM8903
U7 = CDTWIFI10
U8 = RN8-0402
U11 U13 = SOT23_6
U14 = SOIC8N
U15 = SOT23_5
U19 = SOP48-20-720B
U22 = BGA169-BGA153-0_5MM
U23 U24 = DFN2510P10E
U26 = SOT23-5
X2 = X288

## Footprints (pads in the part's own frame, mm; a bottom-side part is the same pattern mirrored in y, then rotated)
AV3-8-5-1
  oval 2.997x2.21 hole 2.997x2.21 unplated: (-4.45,10.8) (-4.45,-10.8)
  oval 2.997x2.007 hole 2.997x2.007 unplated: (-0.95,19.4) (-0.95,-19.4)
  round 1.803 hole 1.803 unplated: (3.05,7.5) (3.05,-7.5)
  rect 3.81x2.311 hole 2.489x1.194: 1(3.25,-15) 2(3.25,0) 3(3.25,15)
  rect 2.489x3.81 hole 1.499x2.489: 6(-0.75,-15) 7(-0.75,0) 8(-0.75,15)
BGA96-32-1609I
  round 0.356 smd: A1(-6,-3.2) A2(-6,-2.4) A3(-6,-1.6) A7(-6,1.6) A8(-6,2.4) A9(-6,3.2) B1(-5.2,-3.2) B2(-5.2,-2.4) B3(-5.2,-1.6) B7(-5.2,1.6) B8(-5.2,2.4) B9(-5.2,3.2) C1(-4.4,-3.2) C2(-4.4,-2.4) C3(-4.4,-1.6) C7(-4.4,1.6) C8(-4.4,2.4) C9(-4.4,3.2) D1(-3.6,-3.2) D2(-3.6,-2.4) D3(-3.6,-1.6) D7(-3.6,1.6) D8(-3.6,2.4) D9(-3.6,3.2) E1(-2.8,-3.2) E2(-2.8,-2.4) E3(-2.8,-1.6) E7(-2.8,1.6) E8(-2.8,2.4) E9(-2.8,3.2) F1(-2,-3.2) F2(-2,-2.4) F3(-2,-1.6) F7(-2,1.6) F8(-2,2.4) F9(-2,3.2) G1(-1.2,-3.2) G2(-1.2,-2.4) G3(-1.2,-1.6) G7(-1.2,1.6) G8(-1.2,2.4) G9(-1.2,3.2) H1(-0.4,-3.2) H2(-0.4,-2.4) H3(-0.4,-1.6) H7(-0.4,1.6) H8(-0.4,2.4) H9(-0.4,3.2) J1(0.4,-3.2) J2(0.4,-2.4) J3(0.4,-1.6) J7(0.4,1.6) J8(0.4,2.4) J9(0.4,3.2) K1(1.2,-3.2) K2(1.2,-2.4) K3(1.2,-1.6) K7(1.2,1.6) K8(1.2,2.4) K9(1.2,3.2) L1(2,-3.2) L2(2,-2.4) L3(2,-1.6) L7(2,1.6) L8(2,2.4) L9(2,3.2) M1(2.8,-3.2) M2(2.8,-2.4) M3(2.8,-1.6) M7(2.8,1.6) M8(2.8,2.4) M9(2.8,3.2) N1(3.6,-3.2) N2(3.6,-2.4) N3(3.6,-1.6) N7(3.6,1.6) N8(3.6,2.4) N9(3.6,3.2) P1(4.4,-3.2) P2(4.4,-2.4) P3(4.4,-1.6) P7(4.4,1.6) P8(4.4,2.4) P9(4.4,3.2) R1(5.2,-3.2) R2(5.2,-2.4) R3(5.2,-1.6) R7(5.2,1.6) R8(5.2,2.4) R9(5.2,3.2) T1(6,-3.2) T2(6,-2.4) T3(6,-1.6) T7(6,1.6) T8(6,2.4) T9(6,3.2)
BGA169-BGA153-0_5MM
  round 0.254 smd: A4(-6.75,-1.75) A6(-6.75,-0.75) A9(-6.75,0.75) A11(-6.75,1.75) AA2(3.25,-2.75) AA3(3.25,-2.25) AA4(3.25,-1.75) AA5(3.25,-1.25) AA6(3.25,-0.75) AA7(3.25,-0.25) AA8(3.25,0.25) AA9(3.25,0.75) AA10(3.25,1.25) AA11(3.25,1.75) AA12(3.25,2.25) AA13(3.25,2.75) AA14(3.25,3.25) AE1(5.25,-3.25) AE14(5.25,3.25) AG2(6.25,-2.75) AG13(6.25,2.75) AH4(6.75,-1.75) AH6(6.75,-0.75) AH9(6.75,0.75) AH11(6.75,1.75) B2(-6.25,-2.75) B13(-6.25,2.75) D1(-5.25,-3.25) D14(-5.25,3.25) H8(-3.25,0.25) H9(-3.25,0.75) H10(-3.25,1.25) H11(-3.25,1.75) H12(-3.25,2.25) H13(-3.25,2.75) H14(-3.25,3.25) J2(-2.75,-2.75) J3(-2.75,-2.25) J4(-2.75,-1.75) J5(-2.75,-1.25) J6(-2.75,-0.75) J7(-2.75,-0.25) J8(-2.75,0.25) J9(-2.75,0.75) J10(-2.75,1.25) J11(-2.75,1.75) J12(-2.75,2.25) J13(-2.75,2.75) J14(-2.75,3.25) K2(-2.25,-2.75) K3(-2.25,-2.25) K4(-2.25,-1.75) K5(-2.25,-1.25) K6(-2.25,-0.75) K7(-2.25,-0.25) K8(-2.25,0.25) K9(-2.25,0.75) K10(-2.25,1.25) K11(-2.25,1.75) K12(-2.25,2.25) K13(-2.25,2.75) K14(-2.25,3.25) L2(-1.75,-2.75) L3(-1.75,-2.25) L4(-1.75,-1.75) L12(-1.75,2.25) L13(-1.75,2.75) L14(-1.75,3.25) M1(-1.25,-3.25) M2(-1.25,-2.75) M3(-1.25,-2.25) M5(-1.25,-1.25) M6(-1.25,-0.75) M7(-1.25,-0.25) M8(-1.25,0.25) M9(-1.25,0.75) M10(-1.25,1.25) M12(-1.25,2.25) M13(-1.25,2.75) M14(-1.25,3.25) N1(-0.75,-3.25) N2(-0.75,-2.75) N3(-0.75,-2.25) N5(-0.75,-1.25) N10(-0.75,1.25) N12(-0.75,2.25) N13(-0.75,2.75) N14(-0.75,3.25) P1(-0.25,-3.25) P2(-0.25,-2.75) P3(-0.25,-2.25) P5(-0.25,-1.25) P10(-0.25,1.25) P12(-0.25,2.25) P13(-0.25,2.75) P14(-0.25,3.25) R1(0.25,-3.25) R2(0.25,-2.75) R3(0.25,-2.25) R5(0.25,-1.25) R10(0.25,1.25) R12(0.25,2.25) R13(0.25,2.75) R14(0.25,3.25) T1(0.75,-3.25) T2(0.75,-2.75) T3(0.75,-2.25) T5(0.75,-1.25) T10(0.75,1.25) T12(0.75,2.25) T13(0.75,2.75) T14(0.75,3.25) U1(1.25,-3.25) U2(1.25,-2.75) U3(1.25,-2.25) U5(1.25,-1.25) U6(1.25,-0.75) U7(1.25,-0.25) U8(1.25,0.25) U9(1.25,0.75) U10(1.25,1.25) U12(1.25,2.25) U13(1.25,2.75) U14(1.25,3.25) V1(1.75,-3.25) V2(1.75,-2.75) V3(1.75,-2.25) V12(1.75,2.25) V13(1.75,2.75) V14(1.75,3.25) W1(2.25,-3.25) W2(2.25,-2.75) W3(2.25,-2.25) W4(2.25,-1.75) W5(2.25,-1.25) W6(2.25,-0.75) W7(2.25,-0.25) W8(2.25,0.25) W9(2.25,0.75) W10(2.25,1.25) W11(2.25,1.75) W12(2.25,2.25) W13(2.25,2.75) W14(2.25,3.25) Y2(2.75,-2.75) Y3(2.75,-2.25) Y4(2.75,-1.75) Y5(2.75,-1.25) Y6(2.75,-0.75) Y7(2.75,-0.25) Y8(2.75,0.25) Y9(2.75,0.75) Y10(2.75,1.25) Y11(2.75,1.75) Y12(2.75,2.25) Y13(2.75,2.75) Y14(2.75,3.25)
  oval 0.203x0.254 smd: AA1(3.25,-3.25) H1(-3.25,-3.25) J1(-2.75,-3.25) K1(-2.25,-3.25) L1(-1.75,-3.25) Y1(2.75,-3.25)
  oval 0.254x0.203 smd: H2(-3.25,-2.75) H3(-3.25,-2.25) H4(-3.25,-1.75) H5(-3.25,-1.25) H6(-3.25,-0.75) H7(-3.25,-0.25)
CDTWIFI
  rect 1.981x1.524 smd: 1(6.087,4.005) 5(6.087,-4.795)
  rect 1.981x1.321 smd: 2(6.087,1.505) 4(6.087,-1.995)
  rect 2.184x1.27 smd: 3(6.189,-0.245)
  rect 2.489x1.397 smd: 6(-6.341,4.5) 7(-6.341,2.5)
CDTWIFI10
  oval 2.54x1.397 smd: 1(-6.1,4.121) 2(-6.1,2.121) 3(-6.1,-0.856) 4(-6.1,-3.015)
  oval 2.032x1.397 smd: 5(6.1,3.621) 6(6.1,1.121) 7(6.1,-2.379) 8(6.1,-5.179)
  oval 1.397x2.54 smd: 9(3.654,-6.5) 10(2.384,-6.5)
DC-002
  oval 2.997x1.803 hole 1.524x0.813: 1(0,0) 2(0,5)
  oval 1.803x2.997 hole 0.813x1.524: 3(-2.7,2.8)
DFN2510P10E
  oval 0.254x0.813 smd: 1(-1,-0.525) 5(1,-0.525) 6(1,0.525) 10(-1,0.525)
  oval 0.229x0.813 smd: 2(-0.5,-0.525) 4(0.5,-0.525) 7(0.5,0.525) 9(-0.5,0.525)
  oval 0.356x0.813 smd: 3(0,-0.525) 8(0,0.525)
HOLE182-142
  round 4.623 hole 3.607: 1(0,0)
HSC0402
  rect 0.508x0.508 smd: 1(-0.406,0) 2(0.406,0)
HSCOX-AMC-TM-A
  rect 0.813x0.813 smd: 1(0,1.35)
  rect 1.168x2.184 smd: 2(-1.326,0) 3(1.326,0)
HSOD323A
  rect 1.118x0.508 smd: 1(1.372,0) 2(-1.372,0)
HSR0402
  rect 0.508x0.508 smd: 1(-0.406,0) 2(0.406,0)
ID-BOARD
  round 1.016 smd: 1(0,0)
LED3C-100C
  rect 1.524x1.524 hole 0.965: 1(0,0)
  round 1.524 hole 0.965: 2(2.54,0) 3(5.08,0)
MJ8-RLY
  round 3.429 hole 3.429 unplated: (-2.794,2.54) (9.906,2.54)
  round 1.27 hole 0.914: 1(0,0) 2(1.016,-1.778) 3(2.032,0) 4(3.048,-1.778) 5(4.064,0) 6(5.08,-1.778) 7(6.096,0) 8(7.112,-1.778) 9(-3.302,-6.604) 10(-1.016,-6.604) 11(8.128,-6.604) 12(10.414,-6.604)
PWC3-RF-A
  rect 1.778x3.962 hole 0.762x2.946: 1(0,0)
  oval 3.454x1.778 hole 2.438x0.762: 2(2.3,4.8)
  oval 1.676x3.454 hole 0.66x2.438: 3(5.8,0)
RN8-0402
  rect 0.305x0.559 smd: 1(-0.762,-0.483) 4(0.762,-0.483) 5(0.762,0.483) 8(-0.762,0.483)
  rect 0.254x0.559 smd: 2(-0.254,-0.483) 3(0.254,-0.483) 6(0.254,0.483) 7(-0.254,0.483)
RSTSW5-R
  rect 0.711x1.118 smd: 1(-1.4,0.925) 2(1.4,0.925)
  rect 1.397x1.118 smd: 3(0,1.075)
  round 0.965 hole 0.559: 4(-1.825,-0.425) 5(1.825,-0.425)
  rect 1.143x0.66 smd: 6(-1.725,-1.05) 7(1.725,-1.05)
RUSB9-180-0726A
  round 1.067 hole 0.66: 1(0,0) 2(0,-2.5) 3(0,-4.5) 4(0,-7) 5(1.8,-7.5) 6(1.8,-5.5) 7(1.8,-3.5) 8(1.8,-1.5) 9(1.8,0.5)
  oval 1.194x2.515 hole 0.787x2.108: 10(-1.81,-8.83) 12(3.61,1.87)
  oval 1.194x1.803 hole 0.787x1.397: 11(3.61,-8.83) 13(-1.81,1.87)
SAC6666
  rect 3.175x1.016 smd: 1(-2.5,0) 2(2.5,0)
SC0402
  rect 0.508x0.508 smd: 1(-0.406,0) 2(0.406,0)
SC0603
  rect 0.762x0.813 smd: 1(-0.699,0) 2(0.699,0)
SC0805
  rect 0.991x1.27 smd: 1(-0.813,0) 2(0.813,0)
SC1206
  rect 1.295x1.651 smd: 1(-1.346,0) 2(1.346,0)
SEN3-100C
  rect 1.27x1.27 hole 0.813: 1(-2.54,0)
  round 1.27 hole 0.813: 2(0,0) 3(2.54,0)
SGM8903
  rect 0.356x1.524 smd: 1(-1.95,-2.921) 2(-1.3,-2.921) 3(-0.65,-2.921) 4(0,-2.921) 5(0.65,-2.921) 6(1.3,-2.921) 7(1.95,-2.921) 8(1.95,2.921) 9(1.3,2.921) 10(0.65,2.921) 11(0,2.921) 12(-0.65,2.921) 13(-1.3,2.921) 14(-1.95,2.921)
SIP5-2MM
  oval 1.168x1.778 hole 0.914: 1(0,0) 2(2,0) 3(4,0) 4(6,0) 5(8,0)
SIP12-2_0MM-1827
  oval 3.175x1.524 hole 1.016: 1(-13.5,5.005) 2(-13.5,3.005) 3(-13.5,1.005) 4(-13.5,-0.995) 5(-13.5,-2.995) 6(-13.5,-4.995)
  oval 2.032x1.27 hole 1.016: 7(13.5,-5.604) 8(13.5,-4.104) 9(13.5,-2.604) 10(13.5,2.681) 11(13.5,4.181) 12(13.5,5.681)
SIP-1P
  round 1.651 hole 0.914: 1(0,0)
SIP-2P
  rect 1.524x1.524 hole 1.143: 1(-1.27,0)
  round 1.524 hole 1.143: 2(1.27,0)
SL0402
  rect 0.483x0.508 smd: 1(-0.394,0) 2(0.394,0)
SL0603
  rect 0.711x0.813 smd: 1(-0.74,0) 2(0.74,0)
SL0805
  rect 0.94x1.27 smd: 1(-0.851,0) 2(0.851,0)
SOIC8N
  rect 0.635x1.905 smd: 1(-1.905,-2.6) 2(-0.635,-2.6) 3(0.635,-2.6) 4(1.905,-2.6) 5(1.905,2.6) 6(0.635,2.6) 7(-0.635,2.6) 8(-1.905,2.6)
  rect 3.505x2.616 smd: 9(0,0)
SOP48-20-720B
  rect 0.254x1.473 smd: 1(-5.75,-9.802) 2(-5.25,-9.802) 3(-4.75,-9.802) 4(-4.25,-9.802) 5(-3.75,-9.802) 6(-3.25,-9.802) 7(-2.75,-9.802) 8(-2.25,-9.802) 9(-1.75,-9.802) 10(-1.25,-9.802) 11(-0.75,-9.802) 12(-0.25,-9.802) 13(0.25,-9.802) 14(0.75,-9.802) 15(1.25,-9.802) 16(1.75,-9.802) 17(2.25,-9.802) 18(2.75,-9.802) 19(3.25,-9.802) 20(3.75,-9.802) 21(4.25,-9.802) 22(4.75,-9.802) 23(5.25,-9.802) 24(5.75,-9.802) 25(5.75,9.802) 26(5.25,9.802) 27(4.75,9.802) 28(4.25,9.802) 29(3.75,9.802) 30(3.25,9.802) 31(2.75,9.802) 32(2.25,9.802) 33(1.75,9.802) 34(1.25,9.802) 35(0.75,9.802) 36(0.25,9.802) 37(-0.25,9.802) 38(-0.75,9.802) 39(-1.25,9.802) 40(-1.75,9.802) 41(-2.25,9.802) 42(-2.75,9.802) 43(-3.25,9.802) 44(-3.75,9.802) 45(-4.25,9.802) 46(-4.75,9.802) 47(-5.25,9.802) 48(-5.75,9.802)
SOT23
  rect 1.016x1.27 smd: 1(-1.016,-1.143) 2(1.016,-1.143) 3(0,1.143)
SOT23-5
  rect 0.711x1.016 smd: 1(-0.95,-1.3) 2(0,-1.3) 3(0.95,-1.3) 4(0.95,1.3) 5(-0.95,1.3)
SOT23_5
  rect 0.635x1.27 smd: 1(-0.95,-1.2) 2(0,-1.2) 3(0.95,-1.2) 4(0.95,1.2) 5(-0.95,1.2)
SOT23_6
  rect 0.635x1.397 smd: 1(-0.95,-1.2) 2(0,-1.2) 3(0.95,-1.2) 4(0.95,1.2) 5(0,1.2) 6(-0.95,1.2)
SOT23A-6L
  rect 0.635x1.27 smd: 1(-0.95,-1.25) 2(0,-1.25) 3(0.95,-1.25) 4(0.95,1.25) 5(0,1.25) 6(-0.95,1.25)
SPSW6-T
  rect 1.829x1.118 smd: 1(-3.1,1.85) 2(3.1,1.85) 3(-3.1,-1.85) 4(3.1,-1.85)
  rect 1.397x0.61 smd: 5(0,2.5) 6(0,-2.5)
SR0402
  rect 0.508x0.508 smd: 1(-0.406,0) 2(0.406,0)
SR0603
  rect 0.711x0.813 smd: 1(-0.737,0) 2(0.737,0)
SR0805
  rect 0.838x1.143 smd: 1(-0.927,0) 2(0.927,0)
SR1206
  rect 1.295x1.6 smd: 1(-1.346,0) 2(1.346,0)
SRN8-0804
  rect 0.279x0.533 smd: 1(-0.762,-0.521) 2(-0.254,-0.521) 3(0.254,-0.521) 4(0.762,-0.521) 5(0.762,0.521) 6(0.254,0.521) 7(-0.254,0.521) 8(-0.762,0.521)
STFM16-50-285
  rect 0.635x1.905 smd: 1(-4.445,-4.381) 2(-3.175,-4.381) 3(-1.905,-4.381) 4(-0.635,-4.381) 5(0.635,-4.381) 6(1.905,-4.381) 7(3.175,-4.381) 8(4.445,-4.381) 9(4.445,4.381) 10(3.175,4.381) 11(1.905,4.381) 12(0.635,4.381) 13(-0.635,4.381) 14(-1.905,4.381) 15(-3.175,4.381) 16(-4.445,4.381)
SWPA4020S
  rect 1.905x3.683 smd: 1(-1.55,0) 2(1.55,0)
SWPA5040S
  rect 1.397x4.191 smd: 1(-1.85,0) 2(1.85,0)
TFBGA395-32-2323
  round 0.356 smd: A1(-8.8,-8.8) A2(-8.8,-8) A3(-8.8,-7.2) A4(-8.8,-6.4) A6(-8.8,-4.8) A8(-8.8,-3.2) A9(-8.8,-2.4) A11(-8.8,-0.8) A12(-8.8,0) A15(-8.8,2.4) A17(-8.8,4) A19(-8.8,5.6) A20(-8.8,6.4) A22(-8.8,8) A23(-8.8,8.8) AA1(7.2,-8.8) AA2(7.2,-8) AA3(7.2,-7.2) AA4(7.2,-6.4) AA5(7.2,-5.6) AA6(7.2,-4.8) AA7(7.2,-4) AA8(7.2,-3.2) AA9(7.2,-2.4) AA10(7.2,-1.6) AA11(7.2,-0.8) AA12(7.2,0) AA13(7.2,0.8) AA14(7.2,1.6) AA15(7.2,2.4) AA16(7.2,3.2) AA17(7.2,4) AA18(7.2,4.8) AA19(7.2,5.6) AA20(7.2,6.4) AA21(7.2,7.2) AA22(7.2,8) AA23(7.2,8.8) AB1(8,-8.8) AB2(8,-8) AB3(8,-7.2) AB4(8,-6.4) AB5(8,-5.6) AB6(8,-4.8) AB7(8,-4) AB8(8,-3.2) AB9(8,-2.4) AB10(8,-1.6) AB11(8,-0.8) AB12(8,0) AB13(8,0.8) AB14(8,1.6) AB15(8,2.4) AB16(8,3.2) AB18(8,4.8) AB20(8,6.4) AB22(8,8) AB23(8,8.8) AC1(8.8,-8.8) AC2(8.8,-8) AC3(8.8,-7.2) AC5(8.8,-5.6) AC6(8.8,-4.8) AC8(8.8,-3.2) AC9(8.8,-2.4) AC11(8.8,-0.8) AC12(8.8,0) AC14(8.8,1.6) AC15(8.8,2.4) AC18(8.8,4.8) AC20(8.8,6.4) AC22(8.8,8) AC23(8.8,8.8) B1(-8,-8.8) B2(-8,-8) B3(-8,-7.2) B4(-8,-6.4) B6(-8,-4.8) B7(-8,-4) B8(-8,-3.2) B9(-8,-2.4) B11(-8,-0.8) B12(-8,0) B14(-8,1.6) B15(-8,2.4) B17(-8,4) B19(-8,5.6) B20(-8,6.4) B22(-8,8) B23(-8,8.8) C1(-7.2,-8.8) C2(-7.2,-8) C3(-7.2,-7.2) C4(-7.2,-6.4) C5(-7.2,-5.6) C6(-7.2,-4.8) C7(-7.2,-4) C8(-7.2,-3.2) C9(-7.2,-2.4) C10(-7.2,-1.6) C11(-7.2,-0.8) C12(-7.2,0) C13(-7.2,0.8) C14(-7.2,1.6) C15(-7.2,2.4) C16(-7.2,3.2) C17(-7.2,4) C18(-7.2,4.8) C19(-7.2,5.6) C20(-7.2,6.4) C21(-7.2,7.2) C22(-7.2,8) D3(-6.4,-7.2) D4(-6.4,-6.4) D5(-6.4,-5.6) D6(-6.4,-4.8) D7(-6.4,-4) D8(-6.4,-3.2) D9(-6.4,-2.4) D10(-6.4,-1.6) D11(-6.4,-0.8) D12(-6.4,0) D13(-6.4,0.8) D14(-6.4,1.6) D15(-6.4,2.4) D16(-6.4,3.2) D17(-6.4,4) D18(-6.4,4.8) D19(-6.4,5.6) D20(-6.4,6.4) D21(-6.4,7.2) D22(-6.4,8) E1(-5.6,-8.8) E2(-5.6,-8) E3(-5.6,-7.2) E4(-5.6,-6.4) E5(-5.6,-5.6) E6(-5.6,-4.8) E15(-5.6,2.4) E16(-5.6,3.2) E17(-5.6,4) E18(-5.6,4.8) E19(-5.6,5.6) E20(-5.6,6.4) E21(-5.6,7.2) E22(-5.6,8) E23(-5.6,8.8) F1(-4.8,-8.8) F2(-4.8,-8) F3(-4.8,-7.2) F4(-4.8,-6.4) F5(-4.8,-5.6) F19(-4.8,5.6) F20(-4.8,6.4) F21(-4.8,7.2) G3(-4,-7.2) G4(-4,-6.4) G5(-4,-5.6) G10(-4,-1.6) G11(-4,-0.8) G12(-4,0) G13(-4,0.8) G14(-4,1.6) G15(-4,2.4) G16(-4,3.2) G17(-4,4) G19(-4,5.6) G20(-4,6.4) G21(-4,7.2) H1(-3.2,-8.8) H2(-3.2,-8) H3(-3.2,-7.2) H4(-3.2,-6.4) H5(-3.2,-5.6) H10(-3.2,-1.6) H11(-3.2,-0.8) H12(-3.2,0) H13(-3.2,0.8) H14(-3.2,1.6) H15(-3.2,2.4) H16(-3.2,3.2) H17(-3.2,4) H19(-3.2,5.6) H20(-3.2,6.4) H21(-3.2,7.2) H22(-3.2,8) H23(-3.2,8.8) J2(-2.4,-8) J3(-2.4,-7.2) J4(-2.4,-6.4) J5(-2.4,-5.6) J6(-2.4,-4.8) J7(-2.4,-4) J10(-2.4,-1.6) J11(-2.4,-0.8) J12(-2.4,0) J13(-2.4,0.8) J14(-2.4,1.6) J15(-2.4,2.4) J16(-2.4,3.2) J17(-2.4,4) J19(-2.4,5.6) J20(-2.4,6.4) J21(-2.4,7.2) J22(-2.4,8) J23(-2.4,8.8) K1(-1.6,-8.8) K2(-1.6,-8) K3(-1.6,-7.2) K4(-1.6,-6.4) K5(-1.6,-5.6) K6(-1.6,-4.8) K7(-1.6,-4) K10(-1.6,-1.6) K11(-1.6,-0.8) K12(-1.6,0) K13(-1.6,0.8) K14(-1.6,1.6) K15(-1.6,2.4) K16(-1.6,3.2) K17(-1.6,4) K19(-1.6,5.6) K20(-1.6,6.4) K21(-1.6,7.2) L1(-0.8,-8.8) L2(-0.8,-8) L3(-0.8,-7.2) L4(-0.8,-6.4) L5(-0.8,-5.6) L6(-0.8,-4.8) L10(-0.8,-1.6) L11(-0.8,-0.8) L12(-0.8,0) L13(-0.8,0.8) L14(-0.8,1.6) L15(-0.8,2.4) L16(-0.8,3.2) L17(-0.8,4) L19(-0.8,5.6) L20(-0.8,6.4) L21(-0.8,7.2) L22(-0.8,8) L23(-0.8,8.8) M2(0,-8) M3(0,-7.2) M4(0,-6.4) M5(0,-5.6) M6(0,-4.8) M8(0,-3.2) M10(0,-1.6) M11(0,-0.8) M12(0,0) M13(0,0.8) M14(0,1.6) M15(0,2.4) M16(0,3.2) M17(0,4) M19(0,5.6) M20(0,6.4) M21(0,7.2) N1(0.8,-8.8) N2(0.8,-8) N3(0.8,-7.2) N4(0.8,-6.4) N5(0.8,-5.6) N6(0.8,-4.8) N8(0.8,-3.2) N10(0.8,-1.6) N11(0.8,-0.8) N12(0.8,0) N13(0.8,0.8) N14(0.8,1.6) N15(0.8,2.4) N16(0.8,3.2) N17(0.8,4) N19(0.8,5.6) N20(0.8,6.4) N21(0.8,7.2) N22(0.8,8) N23(0.8,8.8) P1(1.6,-8.8) P2(1.6,-8) P3(1.6,-7.2) P4(1.6,-6.4) P5(1.6,-5.6) P6(1.6,-4.8) P10(1.6,-1.6) P11(1.6,-0.8) P12(1.6,0) P13(1.6,0.8) P14(1.6,1.6) P15(1.6,2.4) P16(1.6,3.2) P17(1.6,4) P19(1.6,5.6) P20(1.6,6.4) P21(1.6,7.2) R2(2.4,-8) R3(2.4,-7.2) R4(2.4,-6.4) R5(2.4,-5.6) R6(2.4,-4.8) R16(2.4,3.2) R17(2.4,4) R19(2.4,5.6) R20(2.4,6.4) R21(2.4,7.2) R22(2.4,8) R23(2.4,8.8) T1(3.2,-8.8) T2(3.2,-8) T3(3.2,-7.2) T4(3.2,-6.4) T5(3.2,-5.6) T6(3.2,-4.8) T9(3.2,-2.4) T10(3.2,-1.6) T11(3.2,-0.8) T12(3.2,0) T17(3.2,4) T19(3.2,5.6) T20(3.2,6.4) T21(3.2,7.2) U1(4,-8.8) U2(4,-8) U3(4,-7.2) U4(4,-6.4) U5(4,-5.6) U6(4,-4.8) U7(4,-4) U20(4,6.4) U21(4,7.2) U22(4,8) U23(4,8.8) V2(4.8,-8) V3(4.8,-7.2) V4(4.8,-6.4) V5(4.8,-5.6) V6(4.8,-4.8) V7(4.8,-4) V8(4.8,-3.2) V9(4.8,-2.4) V10(4.8,-1.6) V11(4.8,-0.8) V12(4.8,0) V13(4.8,0.8) V14(4.8,1.6) V20(4.8,6.4) V21(4.8,7.2) W1(5.6,-8.8) W2(5.6,-8) W3(5.6,-7.2) W4(5.6,-6.4) W5(5.6,-5.6) W6(5.6,-4.8) W7(5.6,-4) W8(5.6,-3.2) W9(5.6,-2.4) W10(5.6,-1.6) W11(5.6,-0.8) W12(5.6,0) W13(5.6,0.8) W14(5.6,1.6) W15(5.6,2.4) W16(5.6,3.2) W17(5.6,4) W18(5.6,4.8) W19(5.6,5.6) W20(5.6,6.4) W21(5.6,7.2) W22(5.6,8) W23(5.6,8.8) Y1(6.4,-8.8) Y2(6.4,-8) Y3(6.4,-7.2) Y4(6.4,-6.4) Y5(6.4,-5.6) Y6(6.4,-4.8) Y7(6.4,-4) Y8(6.4,-3.2) Y9(6.4,-2.4) Y10(6.4,-1.6) Y11(6.4,-0.8) Y12(6.4,0) Y13(6.4,0.8) Y14(6.4,1.6) Y15(6.4,2.4) Y16(6.4,3.2) Y17(6.4,4) Y18(6.4,4.8) Y19(6.4,5.6) Y20(6.4,6.4) Y21(6.4,7.2) Y22(6.4,8) Y23(6.4,8.8)
unnamed#2
  round 1.016 hole 1.016 unplated: (-3,1.13) (-1.5,1.13) (0,1.13) (1.5,1.13) (3,1.13)
USB4-200-1907
  oval 1.27x1.778 hole 0.914: 1(0,0) 2(2,0) 3(4,0) 4(6,0)
  round 2.032 hole 1.321: 5(-0.73,2.72) 6(6.27,2.72) 7(-0.73,-2.72) 8(6.27,-2.72)
WBC0104-49T
  oval 0.762x1.143 hole 0.508: 1(0,0) 2(1.25,0) 3(2.5,0) 4(3.75,0)
WBC0119-20R-A
  round 1.092 hole 1.092 unplated: (-2.5,2.745) (2.5,2.745)
  rect 0.254x2.591 smd: 1(4.5,5.155) 2(4,5.155) 3(3.5,5.155) 4(3,5.155) 5(2.5,5.155) 6(2,5.155) 7(1.5,5.155) 8(1,5.155) 9(0.5,5.155) 10(0,5.155) 11(-0.5,5.155) 12(-1,5.155) 13(-1.5,5.155) 14(-2,5.155) 15(-2.5,5.155) 16(-3,5.155) 17(-3.5,5.155) 18(-4,5.155) 19(-4.5,5.155)
  oval 1.524x3.302 hole 0.914x2.667: 20(-7.25,4.395) 21(7.25,4.395)
  oval 1.524x2.794 hole 0.914x2.083: 22(-7.25,-1.565) 23(7.25,-1.565)
X288
  rect 1.651x1.27 smd: 1(-1.15,-0.85) 2(1.15,-0.85) 3(1.15,0.85) 4(-1.15,0.85)

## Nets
1V1_CORE: C1.1 C19.1 C22.1 C37.1 C51.1 C82.2 C90.1 C107.1 C120.1 C121.1 C127.1 C189.1 C193.1 C282.1 L3.2 LB12.2 LB21.1 LB31.1 LB113.1 R101.2 U1.J13 U1.J14 U1.K13 U1.K14 U1.L10 U1.L13 U1.L14 U1.M10 U1.M13 U1.M14 U1.N10 U1.N11 U1.N12 U1.N13 U1.N14 U1.P10 U1.P11 U1.P12 U1.P13 U1.P14 U1.P15
1V1_CPU: C21.1 C31.1 C35.1 C41.1 C76.2 C116.1 C132.1 C135.1 C138.1 C242.1 C243.1 C257.1 L2.2 R53.2 U1.H16 U1.H17 U1.J16 U1.J17 U1.K17 U1.L16 U1.L17 U1.M16 U1.M17
1V5_DDR3: C20.1 C28.1 C40.1 C68.1 C84.2 C94.1 C96.1 C97.1 C98.1 C99.1 C100.1 C101.1 C102.1 C103.1 C104.1 C110.1 C137.1 C203.1 C206.1 C207.1 C208.1 C211.1 C212.1 C213.1 C214.1 C215.1 C216.1 C218.1 C219.1 C220.1 C222.1 C223.1 C227.1 C228.1 C229.1 C230.1 C231.1 C232.1 C233.1 C234.1 C235.1 C236.1 C237.1 C238.1 C239.1 C240.1 C258.1 C315.1 C319.1 L4.2 R10.2 R51.1 R54.1 R60.1 R76.1 R78.1 R103.1 U1.J6 U1.J7 U1.K6 U1.K7 U1.L6 U1.N6 U1.P6 U1.T6 U1.T9 U1.T10 U1.U6 U1.U7 U1.V5 U1.V6 U1.V7 U1.V8 U1.V9 U1.V11 U1.V12 U1.V13 U1.V14 U1.W4 U1.W5 U1.W6 U1.W7 U1.Y4 U1.Y5 U1.Y6 U3.A1 U3.A8 U3.B2 U3.C1 U3.C9 U3.D2 U3.D9 U3.E9 U3.F1 U3.G7 U3.H2 U3.H9 U3.K2 U3.K8 U3.N1 U3.N9 U3.R1 U3.R9 U6.A1 U6.A8 U6.B2 U6.C1 U6.C9 U6.D2 U6.D9 U6.E9 U6.F1 U6.G7 U6.H2 U6.H9 U6.K2 U6.K8 U6.N1 U6.N9 U6.R1 U6.R9
3V3: C2.1 C4.1 C13.1 C25.1 C26.1 C27.1 C39.1 C46.1 C53.1 C67.1 C69.1 C91.1 C108.1 C114.1 J18.4 L5.2 Q13.2 R2.1 R3.1 R6.1 R34.1 R65.1 R83.1 R88.2 R105.2 R135.1 R136.2 R140.2 R178.2 U1.V20 U1.W20 U11.4 U13.4 U15.4
3V3_IR: C47.1 C177.1 D3.3 J3.2 R178.1
3V3_MOS: C74.1 C197.1 C198.1 C199.1 C245.1 C283.1 D1.2 D9.2 D19.2 J25.10 J25.12 LB1.2 LB4.2 LB7.2 LB8.2 LB14.1 LB17.2 LB18.1 LB20.1 LB22.1 LB35.1 Q13.3 R25.1 R26.1 R30.1 R41.2 R86.1 U1.D10 U1.D11 U1.D12 U1.E18 U1.F5 U1.H19 U1.J19 U1.M19 U1.N19
3V3_MOS_FLASH: C29.1 C36.1 C63.1 C93.1 C105.1 C142.1 C143.1 C275.1 C323.1 C324.1 D1.1 R12.1 R29.1 R57.2 R58.1 R80.1 R86.2 R91.1 R176.1 R177.1 R188.1 R189.1 R202.1 R203.1 R212.1 R215.1 U19.1 U19.12 U19.24 U19.34 U19.37 U22.AA3 U22.AA5 U22.K6 U22.M6 U22.N5 U22.T10 U22.U9 U22.W4 U22.Y4
3V3_WIFI: C15.1 C61.1 J2.5 LB4.1 U2.5 U7.8
5V0: C6.1 C58.1 C59.1 C111.1 C112.1 D2.2 J5.1 Q14.2 R4.1 R81.2 R144.1 U14.2
5V0_MOS: C377.1 D20.2 LB2.2 Q14.3 R179.1 R220.2 U26.1
5V0_MOS_HDMI: C150.1 D20.1 J26.18 R186.2 R187.2 U4.5
AVDD11_PLL012: C12.1 C185.1 LB21.2 U1.P17
AVDD11_USB3: C16.1 C119.1 LB113.2 U1.R16 U1.R17 U1.T17
AVDD33_ADAC: C188.1 C194.1 LB35.2 R39.2 U1.E19
AVDD33_PLL01: C14.1 C186.1 LB22.2 U1.R19
AVDD33_USB2: C3.1 LB17.1 U1.K19
AVDD33_USB3: C18.1 LB18.2 U1.W17 U1.W18
GND: C1.2 C2.2 C3.2 C4.2 C5.2 C7.2 C8.2 C9.2 C10.2 C11.2 C12.2 C13.2 C14.2 C15.2 C16.2 C17.2 C18.2 C19.2 C20.2 C21.2 C22.2 C23.2 C24.2 C25.2 C26.2 C27.2 C28.2 C29.2 C30.2 C31.2 C33.1 C34.2 C35.2 C36.2 C37.2 C38.1 C39.2 C40.2 C41.2 C42.2 C43.2 C44.2 C45.2 C46.2 C47.2 C48.2 C50.2 C51.2 C53.2 C56.2 C57.2 C58.2 C59.2 C60.2 C61.2 C63.2 C67.2 C68.2 C69.2 C71.2 C72.2 C74.2 C77.2 C78.2 C79.2 C85.2 C88.2 C89.2 C90.2 C91.2 C93.2 C94.2 C96.2 C97.2 C98.2 C99.2 C100.2 C101.2 C102.2 C103.2 C104.2 C105.2 C107.2 C108.2 C110.2 C111.2 C112.2 C114.2 C115.2 C116.2 C119.2 C120.2 C121.2 C123.2 C124.2 C127.2 C132.2 C135.2 C137.2 C138.2 C140.2 C142.2 C143.2 C149.2 C150.2 C153.2 C154.2 C158.2 C164.2 C177.2 C182.2 C185.2 C186.2 C188.2 C189.2 C193.2 C194.2 C197.2 C198.2 C199.2 C203.2 C206.2 C211.2 C212.2 C213.2 C214.2 C215.2 C216.2 C218.2 C219.2 C220.2 C227.2 C228.2 C229.2 C230.2 C231.2 C232.2 C233.2 C234.2 C235.2 C236.2 C237.2 C238.2 C239.2 C240.2 C242.2 C243.2 C245.2 C248.2 C250.1 C251.2 C255.1 C257.2 C258.2 C264.2 C265.2 C270.2 C271.2 C275.2 C281.2 C282.2 C283.2 C289.2 C297.2 C307.2 C308.2 C310.2 C313.2 C314.2 C315.2 C316.2 C317.2 C319.2 C320.2 C323.2 C324.2 C328.2 C330.2 C334.2 C336.2 C339.2 C363.2 C364.2 C365.2 C372.2 C377.2 D3.2 D4.2 D5.2 D9.1 J1.2 J1.3 J2.2 J2.7 J2.9 J2.10 J2.12 J3.4 J4.1 J6.1 J8.2 J8.3 J9.2 J9.3 J10.2 J10.3 J12.4 J12.5 J12.6 J12.7 J12.8 J18.1 J26.2 J26.5 J26.8 J26.11 J26.17 J26.20 J26.21 J26.22 J26.23 J28.4 J28.7 J28.10 J28.11 J28.12 J28.13 J34.6 J34.7 J34.8 LED1.2 Q1.2 Q2.2 Q4.2 R8.1 R9.2 R13.1 R24.2 R32.1 R33.2 R38.1 R40.2 R44.2 R45.2 R46.1 R49.2 R50.2 R52.2 R55.2 R56.1 R61.1 R71.1 R75.2 R77.2 R82.1 R83.2 R84.2 R85.2 R87.1 R89.2 R91.2 R99.1 R100.2 R104.2 R106.1 R107.2 R145.2 R146.2 R173.2 R183.2 R229.2 RN5.2 RN5.7 RN7.2 RN7.7 RN10.2 RN10.7 RN14.2 RN14.7 S1.1 S1.3 S1.4 S1.5 S1.6 S1.7 S2.3 S2.4 S2.5 S2.6 U1.A1 U1.A2 U1.A3 U1.A23 U1.AA2 U1.AA3 U1.AA8 U1.AA13 U1.AA14 U1.AA15 U1.AA17 U1.AA18 U1.AA20 U1.AB1 U1.AB4 U1.AB6 U1.AB10 U1.AB12 U1.AC1 U1.AC3 U1.AC5 U1.AC9 U1.AC11 U1.AC23 U1.B3 U1.B8 U1.B20 U1.B23 U1.C3 U1.C4 U1.C6 U1.C8 U1.C13 U1.C15 U1.C17 U1.C20 U1.C21 U1.C22 U1.D4 U1.D6 U1.D9 U1.D13 U1.D14 U1.D15 U1.D17 U1.D19 U1.D20 U1.D21 U1.D22 U1.E4 U1.E16 U1.E17 U1.E21 U1.E22 U1.F4 U1.F21 U1.G3 U1.G4 U1.G12 U1.G13 U1.G16 U1.G20 U1.H3 U1.H10 U1.H11 U1.H12 U1.H13 U1.H14 U1.H15 U1.H20 U1.J2 U1.J10 U1.J11 U1.J12 U1.J15 U1.J20 U1.K1 U1.K3 U1.K5 U1.K10 U1.K11 U1.K12 U1.K15 U1.K16 U1.L3 U1.L4 U1.L11 U1.L12 U1.L15 U1.L20 U1.L21 U1.M6 U1.M8 U1.M11 U1.M12 U1.M15 U1.M20 U1.N2 U1.N3 U1.N5 U1.N15 U1.N16 U1.N17 U1.P1 U1.P5 U1.P16 U1.P19 U1.P20 U1.R2 U1.R4 U1.R6 U1.R20 U1.T1 U1.T11 U1.U2 U1.U5 U1.U20 U1.V4 U1.V10 U1.V21 U1.W3 U1.W8 U1.W11 U1.W13 U1.W15 U1.W19 U1.W21 U1.Y1 U1.Y3 U1.Y7 U1.Y9 U1.Y18 U1.Y20 U1.Y23 U2.1 U2.6 U3.A9 U3.B1 U3.B3 U3.B9 U3.D1 U3.D8 U3.E1 U3.E2 U3.E8 U3.F9 U3.G1 U3.G8 U3.G9 U3.J2 U3.J8 U3.M1 U3.M9 U3.P1 U3.P9 U3.T1 U3.T9 U4.2 U5.1 U5.4 U5.10 U5.14 U6.A9 U6.B1 U6.B3 U6.B9 U6.D1 U6.D8 U6.E1 U6.E2 U6.E8 U6.F9 U6.G1 U6.G8 U6.G9 U6.J2 U6.J8 U6.M1 U6.M9 U6.P1 U6.P9 U6.T1 U6.T9 U7.1 U7.5 U11.2 U13.2 U14.4 U14.9 U15.2 U19.2 U19.13 U19.23 U19.25 U19.36 U19.48 U22.AA4 U22.AA6 U22.K4 U22.M7 U22.P5 U22.R10 U22.U8 U22.Y2 U22.Y5 U23.3 U23.8 U24.3 U24.8 U26.2 X2.2 X2.4
VDD_AUDIO: C158.1 C320.1 R48.1 R66.2 R179.2 U5.9
ADAC_VOUTL: C350.2 R50.1 U1.B22
ADAC_VOUTR: C351.1 R183.1 U1.A22
AUDIO_L: C339.1 J34.2 R72.2
AUDIO_R: C140.1 J34.1 R74.1
CORE_CTRL: R23.2 U1.H22
CPU_CTRL: R21.2 U1.H23
CVBS: C79.1 C80.1 L6.1 R9.1 U1.E23
CVBS_OUT: C17.1 C80.2 D9.3 J34.3 L6.2
DDR_ADDR0: RN2.1 RN11.8 U1.AC14
DDR_ADDR0_A: RN2.8 U3.N3
DDR_ADDR0_B: RN11.1 U6.N3
DDR_ADDR1: RN4.3 RN13.6 U1.Y10
DDR_ADDR1_A: RN4.6 U3.P7
DDR_ADDR1_B: RN13.3 U6.P7
DDR_ADDR2: RN1.4 RN9.5 U1.W14
DDR_ADDR2_A: RN1.5 U3.P3
DDR_ADDR2_B: RN9.4 U6.P3
DDR_ADDR3: RN2.2 RN11.7 U1.AB14
DDR_ADDR3_A: RN2.7 U3.N2
DDR_ADDR3_B: RN11.2 U6.N2
DDR_ADDR4: RN4.4 RN13.5 U1.W10
DDR_ADDR4_A: RN4.5 U3.P8
DDR_ADDR4_B: RN13.4 U6.P8
DDR_ADDR5: RN2.3 RN11.6 U1.Y16
DDR_ADDR5_A: RN2.6 U3.P2
DDR_ADDR5_B: RN11.3 U6.P2
DDR_ADDR6: RN4.2 RN13.7 U1.AA10
DDR_ADDR6_A: RN4.7 U3.R8
DDR_ADDR6_B: RN13.2 U6.R8
DDR_ADDR7: RN2.4 RN11.5 U1.AA16
DDR_ADDR7_A: RN2.5 U3.R2
DDR_ADDR7_B: RN11.4 U6.R2
DDR_ADDR8: RN4.1 RN13.8 U1.AB11
DDR_ADDR8_A: RN4.8 U3.T8
DDR_ADDR8_B: RN13.1 U6.T8
DDR_ADDR9: RN1.2 RN9.7 U1.AA12
DDR_ADDR9_A: RN1.7 U3.R3
DDR_ADDR9_B: RN9.2 U6.R3
DDR_ADDR10: RN6.3 RN8.6 U1.Y8
DDR_ADDR10_A: RN6.6 U3.L7
DDR_ADDR10_B: RN8.3 U6.L7
DDR_ADDR11: RN5.3 RN10.6 U1.Y11
DDR_ADDR11_A: RN5.6 U3.R7
DDR_ADDR11_B: RN10.3 U6.R7
DDR_ADDR12: RN6.2 RN8.7 U1.AB9
DDR_ADDR12_A: RN6.7 U3.N7
DDR_ADDR12_B: RN8.2 U6.N7
DDR_ADDR13: RN1.3 RN9.6 U1.Y15
DDR_ADDR13_A: RN1.6 U3.T3
DDR_ADDR13_B: RN9.3 U6.T3
DDR_ADDR14: RN5.4 RN10.5 U1.AA11
DDR_ADDR14_A: RN5.5 U3.T7
DDR_ADDR14_B: RN10.4 U6.T7
DDR_ADDR15: RN5.1 RN10.8 U1.W12
DDR_ADDR15_A: RN5.8 U3.M7
DDR_ADDR15_B: RN10.1 U6.M7
DDR_BA0: RN7.4 RN14.5 U1.AC15
DDR_BA0_A: RN7.5 U3.M2
DDR_BA0_B: RN14.4 U6.M2
DDR_BA1: RN6.1 RN8.8 U1.AA9
DDR_BA1_A: RN6.8 U3.N8
DDR_BA1_B: RN8.1 U6.N8
DDR_BA2: RN3.2 RN12.7 U1.Y12
DDR_BA2_A: RN3.7 U3.M3
DDR_BA2_B: RN12.2 U6.M3
DDR_CASN: RN3.4 RN12.5 U1.Y14
DDR_CASN_A: RN3.5 U3.K3
DDR_CASN_B: RN12.4 U6.K3
DDR_CKE: R38.2 RN6.4 RN8.5 U1.W9
DDR_CKE_A: RN6.5 U3.K9
DDR_CKE_B: RN8.4 U6.K9
DDR_CLK0N: R11.1 R35.1 U3.K7
DDR_CLK0P: R15.2 R18.1 U3.J7
DDR_CLK1N: R16.1 R37.1 U6.K7
DDR_CLK1P: R17.2 R36.1 U6.J7
DDR_CSN: RN3.1 RN12.8 U1.AC12
DDR_CSN_A: RN3.8 U3.L2
DDR_CSN_B: RN12.1 U6.L2
DDR_DM0: U1.K4 U3.E7
DDR_DM1: U1.L5 U3.D3
DDR_DM2: U1.AA1 U6.E7
DDR_DM3: U1.Y2 U6.D3
DDR_DQ0: U1.H4 U3.E3
DDR_DQ1: U1.N1 U3.F7
DDR_DQ2: U1.H1 U3.F2
DDR_DQ3: U1.P3 U3.F8
DDR_DQ4: U1.H5 U3.H3
DDR_DQ5: U1.R3 U3.H8
DDR_DQ6: U1.H2 U3.G2
DDR_DQ7: U1.P2 U3.H7
DDR_DQ8: U1.M4 U3.D7
DDR_DQ9: U1.K2 U3.C3
DDR_DQ10: U1.M5 U3.C8
DDR_DQ11: U1.J3 U3.C2
DDR_DQ12: U1.N4 U3.A7
DDR_DQ13: U1.J4 U3.A2
DDR_DQ14: U1.P4 U3.B8
DDR_DQ15: U1.J5 U3.A3
DDR_DQ16: U1.T5 U6.E3
DDR_DQ17: U1.AA5 U6.F7
DDR_DQ18: U1.T2 U6.F2
DDR_DQ19: U1.AB5 U6.F8
DDR_DQ20: U1.R5 U6.H3
DDR_DQ21: U1.AC6 U6.H8
DDR_DQ22: U1.T3 U6.G2
DDR_DQ23: U1.AA6 U6.H7
DDR_DQ24: U1.AA4 U6.D7
DDR_DQ25: U1.U1 U6.C3
DDR_DQ26: U1.AB3 U6.C8
DDR_DQ27: U1.U3 U6.C2
DDR_DQ28: U1.AC2 U6.A7
DDR_DQ29: U1.T4 U6.A2
DDR_DQ30: U1.AB2 U6.B8
DDR_DQ31: U1.U4 U6.A3
DDR_DQS0N: U1.L1 U3.G3
DDR_DQS0P: U1.L2 U3.F3
DDR_DQS1N: U1.M3 U3.B7
DDR_DQS1P: U1.M2 U3.C7
DDR_DQS2N: U1.V2 U6.G3
DDR_DQS2P: U1.V3 U6.F3
DDR_DQS3N: U1.W2 U6.B7
DDR_DQS3P: U1.W1 U6.C7
DDR_ODT: RN7.3 RN14.6 U1.AB15
DDR_ODT_A: RN7.6 U3.K1
DDR_ODT_B: RN14.3 U6.K1
DDR_PLL: C11.1 C264.1 C270.1 LB7.1 U1.N8 U1.T12
DDR_RASN: RN7.1 RN14.8 U1.AB16
DDR_RASN_A: RN7.8 U3.J3
DDR_RASN_B: RN14.1 U6.J3
DDR_RESETN: RN1.1 RN9.8 U1.AB13
DDR_RESETN_A: C313.1 R60.2 RN1.8 U3.T2
DDR_RESETN_B: C314.1 R76.2 RN9.1 U6.T2
DDR_VREF_CA_A: C207.2 C289.1 R51.2 R55.1 U3.M8
DDR_VREF_CA_B: C222.2 C310.1 R103.2 R107.1 U6.M8
DDR_VREF_DQ_A: C208.2 C271.1 R54.2 R75.1 U3.H1
DDR_VREF_DQ_B: C223.2 C308.1 R78.2 R84.1 U6.H1
DDR_WEN: RN3.3 RN12.6 U1.Y13
DDR_WEN_A: RN3.6 U3.L3
DDR_WEN_B: RN12.3 U6.L3
FE_1V1: C248.1 U1.G10
FE_3V3: C7.1 LB8.1 U1.E5
HDMI_TX0N: J26.9 U1.D16 U24.2 U24.9
HDMI_TX0P: J26.7 U1.C16 U24.1 U24.10
HDMI_TX1N: J26.6 U1.B15 U23.5 U23.6
HDMI_TX1P: J26.4 U1.A15 U23.4 U23.7
HDMI_TX2N: J26.3 U1.C14 U23.2 U23.9
HDMI_TX2P: J26.1 U1.B14 U23.1 U23.10
HDMI_TX_1V1: C78.1 C164.1 C251.1 C281.1 LB12.1 U1.G14 U1.G15
HDMI_TX_3V3: C57.1 C77.1 LB1.1 U1.E15
HDMI_TX_CEC: J26.13 R268.2 U1.C18 U4.3
HDMI_TX_HOTPLUG: C149.1 J26.19 R8.2 U1.B19 U4.4
HDMI_TX_SCL: J26.15 R186.1 U1.D18 U4.1
HDMI_TX_SDA: J26.16 R187.1 U1.A19 U4.6
HDMI_TXCN: J26.12 U1.B17 U24.5 U24.6
HDMI_TXCP: J26.10 U1.A17 U24.4 U24.7
IR_IN: D3.1 J3.3 R140.1 U1.Y21
LED0_BASE: R26.2 R67.2 U1.B2
LED0_LINK_ACT: R30.2 R79.2 U1.B1
LED_GREEN: R3.2 R22.1 R77.1 U1.AB22
LED_GREEN_1: J3.1 LED1.3 Q1.3 R2.2
LED_RED: R31.1 R49.1 R65.2 U1.AC22
LED_RED_1: J3.5 LED1.1 Q2.3 R34.2
MUTE_CTRL: R90.1 U1.C19
NF_ALE_EMMC_PWREN: U1.N20 U19.17
NF_CLE: U1.N21 U19.16
